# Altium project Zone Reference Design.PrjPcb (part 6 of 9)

## Sheet IO Management.SchDoc
size 431 x 279 mm; Date: Not shown in title block; ApprovedBy: Not shown in title block; CheckedBy: Not shown in title block; Author: Not shown in title block; CompanyName: Not shown in title block; Engineer: Not shown in title block; Organization: Not shown in title block; Address1: Not shown in title block; Address2: Not shown in title block; Address3: Not shown in title block; Address4: Not shown in title block; DocumentNumber: 1; Revision: Use project parameter SCH_Rev; SheetNumber: 26; SheetTotal: 30; PageSetup: Record=PageOptions¦CenterHorizontal=True¦CenterVertical=True¦PrintScale=1.00¦XCorrection=1.00¦YCorrection=1.00¦PrintKind=0¦BorderSize=5000000¦LeftOffset=0¦BottomOffset=0¦Orientation=2¦PaperLength=1000¦PaperWidth=1000¦Scale=100¦PaperSource=15¦PrintQuality=600¦MediaType=1¦DitherType=10¦PaperKind=Letter¦PrintScaleMode=1
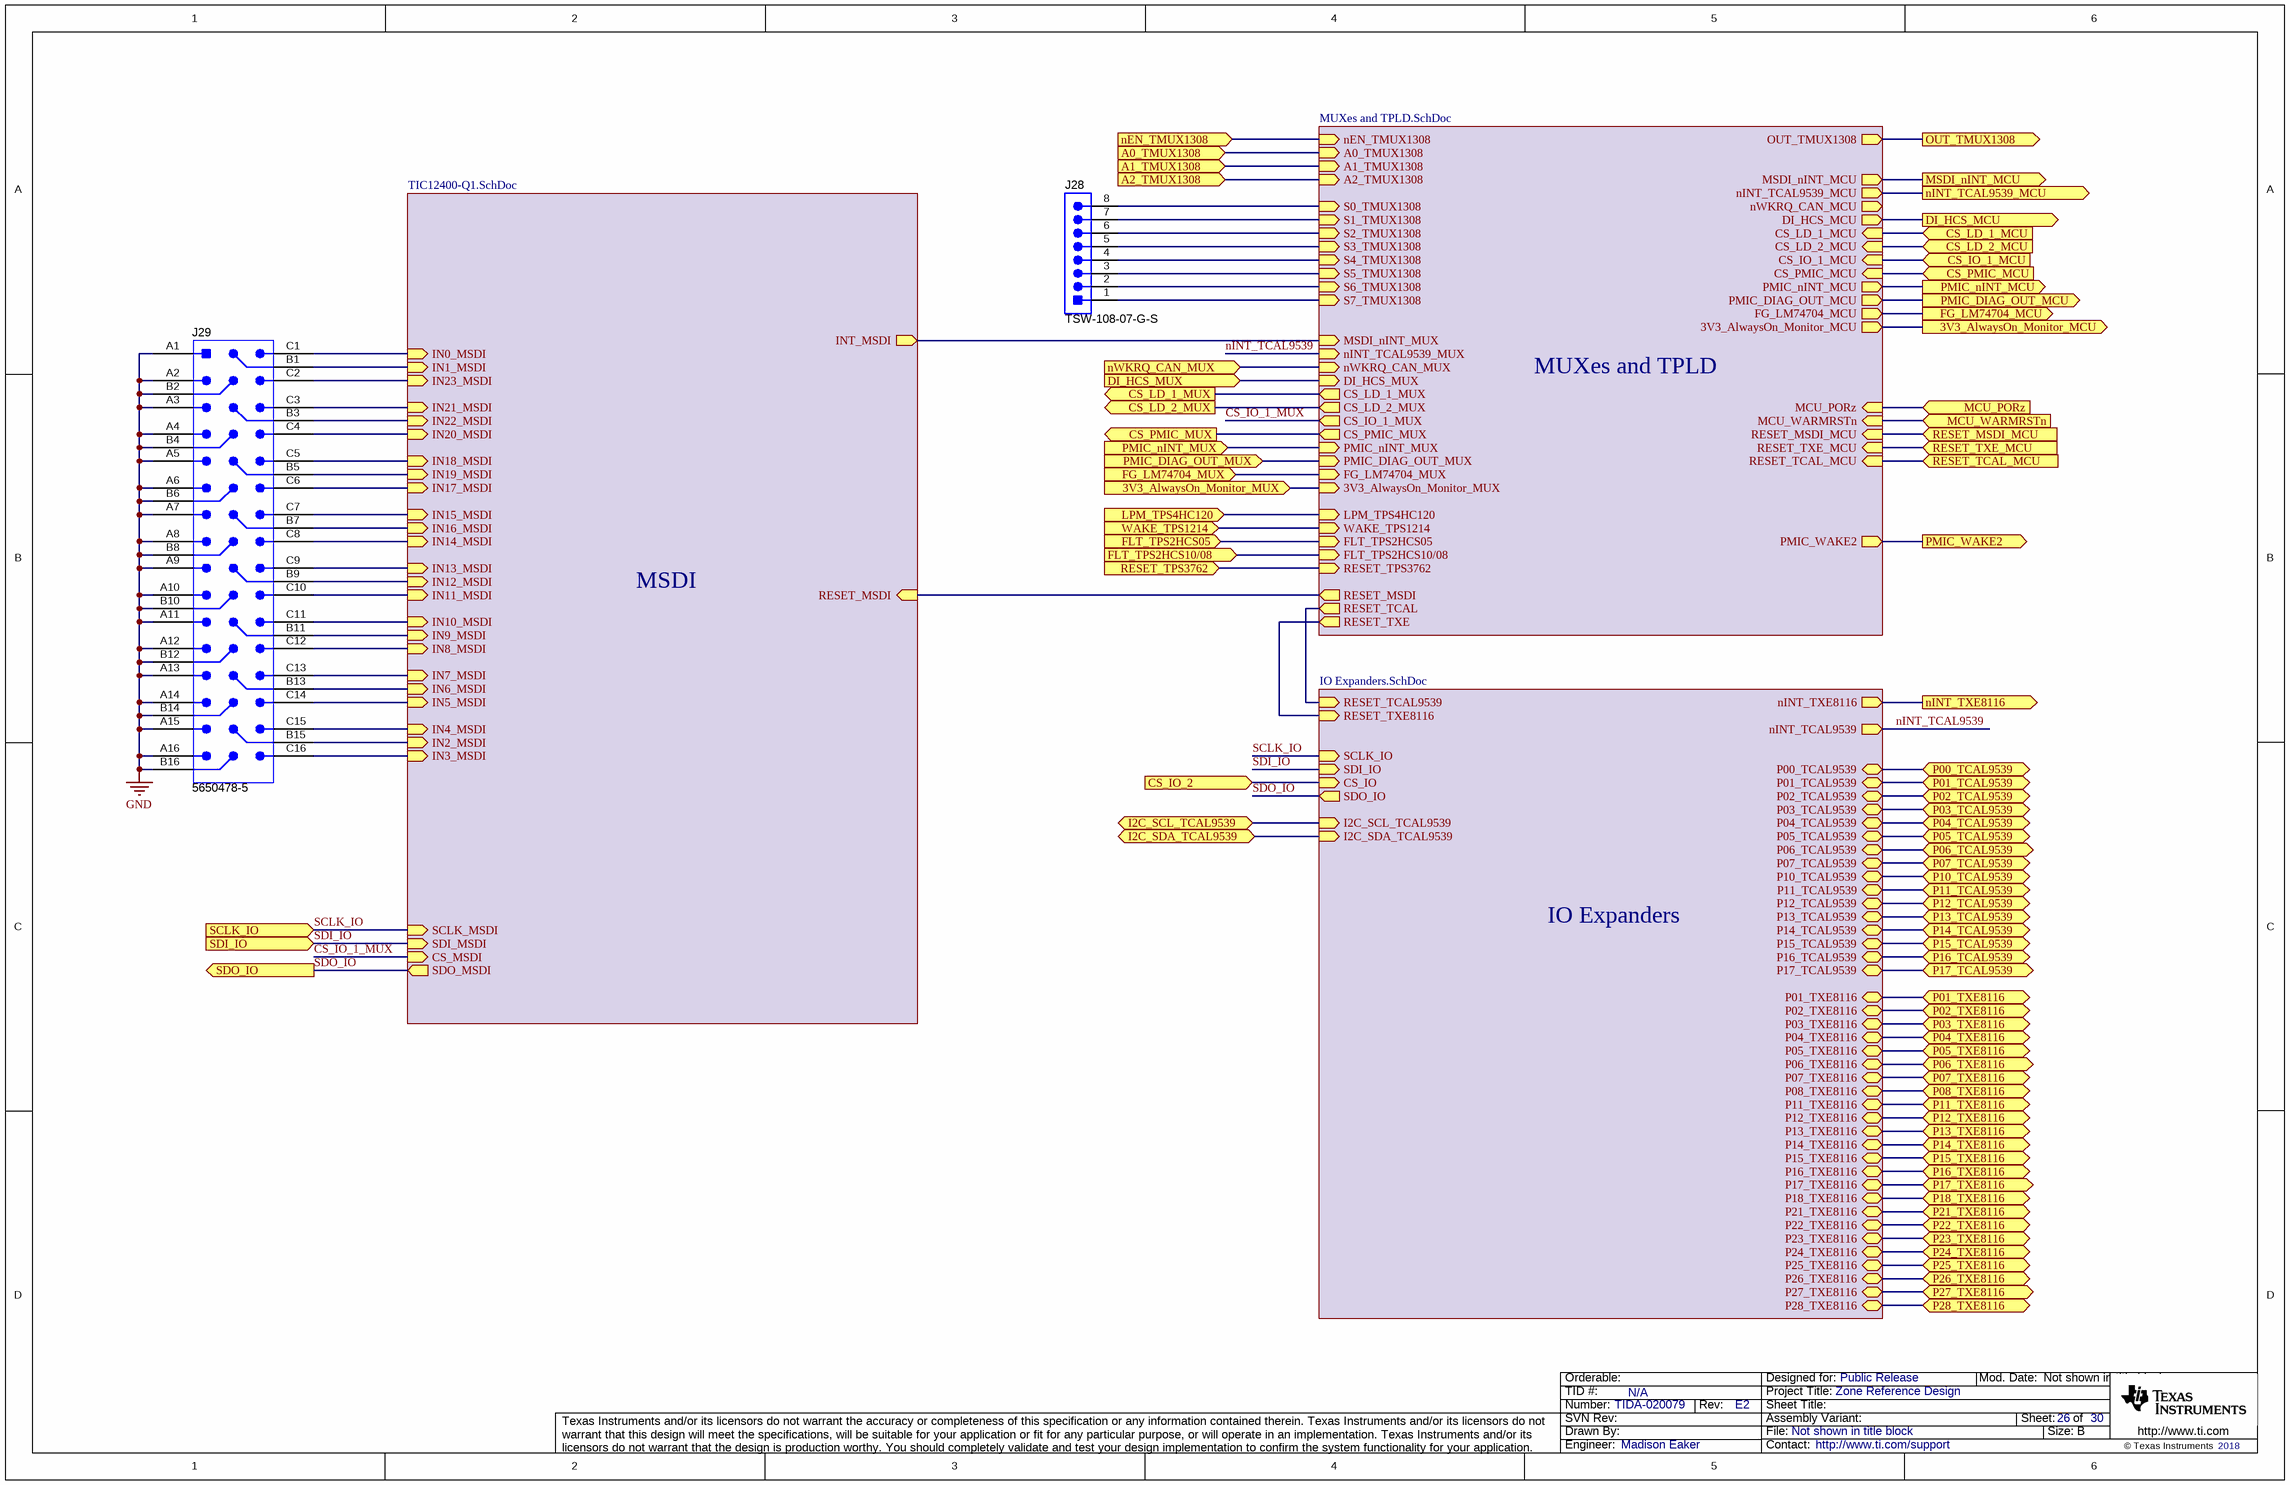
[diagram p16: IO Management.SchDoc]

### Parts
J28  TSW-108-07-G-S  [TSW-108-07-G-S]
J29  5650478-5  [TE_5650478-5]

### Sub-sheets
IO Expanders = IO Expanders.SchDoc: SCLK_IO (in), SDI_IO (in), SDO_IO (out), CS_IO (in), nINT_TXE8116 (out), RESET_TCAL9539 (in), I2C_SCL_TCAL9539 (in), I2C_SDA_TCAL9539 (in), nINT_TCAL9539 (out), RESET_TXE8116 (in), P00_TCAL9539 (bidir), P01_TCAL9539 (bidir), P02_TCAL9539 (bidir), P03_TCAL9539 (bidir), P04_TCAL9539 (bidir), P05_TCAL9539 (bidir), P06_TCAL9539 (bidir), P07_TCAL9539 (bidir), P10_TCAL9539 (bidir), P11_TCAL9539 (bidir), P12_TCAL9539 (bidir), P13_TCAL9539 (bidir), P14_TCAL9539 (bidir), P15_TCAL9539 (bidir), P16_TCAL9539 (bidir), P17_TCAL9539 (bidir), P01_TXE8116 (bidir), P02_TXE8116 (bidir), P03_TXE8116 (bidir), P04_TXE8116 (bidir), P05_TXE8116 (bidir), P06_TXE8116 (bidir), P07_TXE8116 (bidir), P11_TXE8116 (bidir), P12_TXE8116 (bidir), P13_TXE8116 (bidir), P14_TXE8116 (bidir), P15_TXE8116 (bidir), P16_TXE8116 (bidir), P17_TXE8116 (bidir), P08_TXE8116 (bidir), P18_TXE8116 (bidir), P21_TXE8116 (bidir), P22_TXE8116 (bidir), P23_TXE8116 (bidir), P24_TXE8116 (bidir), P25_TXE8116 (bidir), P26_TXE8116 (bidir), P27_TXE8116 (bidir), P28_TXE8116 (bidir)
MSDI = TIC12400-Q1.SchDoc: IN0_MSDI (in), IN1_MSDI (in), IN2_MSDI (in), IN3_MSDI (in), IN4_MSDI (in), IN5_MSDI (in), IN6_MSDI (in), IN7_MSDI (in), IN8_MSDI (in), IN9_MSDI (in), IN10_MSDI (in), IN11_MSDI (in), IN12_MSDI (in), IN13_MSDI (in), IN14_MSDI (in), IN15_MSDI (in), IN16_MSDI (in), IN17_MSDI (in), IN18_MSDI (in), IN19_MSDI (in), IN20_MSDI (in), IN21_MSDI (in), IN22_MSDI (in), IN23_MSDI (in), RESET_MSDI (in), SCLK_MSDI (in), SDI_MSDI (in), SDO_MSDI (out), CS_MSDI (in), INT_MSDI (out)
MUXes and TPLD = MUXes and TPLD.SchDoc: OUT_TMUX1308 (out), nEN_TMUX1308 (in), MSDI_nINT_MUX (in), MSDI_nINT_MCU (out), S0_TMUX1308 (in), S1_TMUX1308 (in), S2_TMUX1308 (in), S3_TMUX1308 (in), S4_TMUX1308 (in), S5_TMUX1308 (in), S6_TMUX1308 (in), S7_TMUX1308 (in), A0_TMUX1308 (in), A1_TMUX1308 (in), A2_TMUX1308 (in), PMIC_WAKE2 (out), nINT_TCAL9539_MUX (in), nINT_TCAL9539_MCU (out), MCU_PORz (in), MCU_WARMRSTn (in), RESET_MSDI_MCU (in), RESET_TXE_MCU (in), RESET_TCAL_MCU (in), RESET_MSDI (out), RESET_TCAL (out), RESET_TXE (out), DI_HCS_MUX (in), DI_HCS_MCU (out), LPM_TPS4HC120 (in), 3V3_AlwaysOn_Monitor_MUX (in), 3V3_AlwaysOn_Monitor_MCU (out), RESET_TPS3762 (in), WAKE_TPS1214 (in), FLT_TPS2HCS05 (in), FLT_TPS2HCS10/08  (in), CS_LD_1_MUX (out), CS_LD_2_MUX (out), CS_IO_1_MUX (out), CS_LD_1_MCU (in), CS_LD_2_MCU (in), CS_IO_1_MCU (in), CS_PMIC_MUX (out), CS_PMIC_MCU (in), PMIC_nINT_MUX (in), PMIC_DIAG_OUT_MUX (in), FG_LM74704_MUX (in), PMIC_nINT_MCU (out), PMIC_DIAG_OUT_MCU (out), FG_LM74704_MCU (out), nWKRQ_CAN_MUX (in), nWKRQ_CAN_MCU (out)

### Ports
3V3_AlwaysOn_Monitor_MCU (out), 3V3_AlwaysOn_Monitor_MUX (in), A0_TMUX1308 (in), A1_TMUX1308 (in), A2_TMUX1308 (in), CS_IO_1_MCU (in), CS_IO_2 (in), CS_LD_1_MCU (in), CS_LD_1_MUX (out), CS_LD_2_MCU (in), CS_LD_2_MUX (out), CS_PMIC_MCU (in), CS_PMIC_MUX (out), DI_HCS_MCU (out), DI_HCS_MUX (in), FG_LM74704_MCU (out), FG_LM74704_MUX (in), FLT_TPS2HCS05 (in), FLT_TPS2HCS10/08  (in), I2C_SCL_TCAL9539 (bidir), I2C_SDA_TCAL9539 (bidir), LPM_TPS4HC120 (in), MCU_PORz (in), MCU_WARMRSTn (in), MSDI_nINT_MCU (out), nEN_TMUX1308 (in), nINT_TCAL9539_MCU (out), nINT_TXE8116 (out), nWKRQ_CAN_MUX (in), OUT_TMUX1308 (out), P00_TCAL9539 (bidir), P01_TCAL9539 (bidir), P01_TXE8116 (bidir), P02_TCAL9539 (bidir), P02_TXE8116 (bidir), P03_TCAL9539 (bidir), P03_TXE8116 (bidir), P04_TCAL9539 (bidir), P04_TXE8116 (bidir), P05_TCAL9539 (bidir), P05_TXE8116 (bidir), P06_TCAL9539 (bidir), P06_TXE8116 (bidir), P07_TCAL9539 (bidir), P07_TXE8116 (bidir), P08_TXE8116 (bidir), P10_TCAL9539 (bidir), P11_TCAL9539 (bidir), P11_TXE8116 (bidir), P12_TCAL9539 (bidir), P12_TXE8116 (bidir), P13_TCAL9539 (bidir), P13_TXE8116 (bidir), P14_TCAL9539 (bidir), P14_TXE8116 (bidir), P15_TCAL9539 (bidir), P15_TXE8116 (bidir), P16_TCAL9539 (bidir), P16_TXE8116 (bidir), P17_TCAL9539 (bidir), P17_TXE8116 (bidir), P18_TXE8116 (bidir), P21_TXE8116 (bidir), P22_TXE8116 (bidir), P23_TXE8116 (bidir), P24_TXE8116 (bidir), P25_TXE8116 (bidir), P26_TXE8116 (bidir), P27_TXE8116 (bidir), P28_TXE8116 (bidir), PMIC_DIAG_OUT_MCU (out), PMIC_DIAG_OUT_MUX (in), PMIC_nINT_MCU (out), PMIC_nINT_MUX (in), PMIC_WAKE2 (out), RESET_MSDI_MCU (in), RESET_TCAL_MCU (in), RESET_TPS3762 (in), RESET_TXE_MCU (in), SCLK_IO (in), SDI_IO (in), SDO_IO (out), WAKE_TPS1214 (in)

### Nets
GND: J29.A1 J29.A2 J29.A3 J29.A4 J29.A5 J29.A6 J29.A7 J29.A8 J29.A9 J29.A10 J29.A11 J29.A12 J29.A13 J29.A14 J29.A15 J29.A16 J29.B2 J29.B4 J29.B6 J29.B8 J29.B10 J29.B12 J29.B14 J29.B16
3V3_ADC: port 3V3_AlwaysOn_Monitor_MUX, sheet MUXes and TPLD/3V3_AlwaysOn_Monitor_MUX
3V3_AlwaysOn_Monitor_MCU: port 3V3_AlwaysOn_Monitor_MCU, sheet MUXes and TPLD/3V3_AlwaysOn_Monitor_MCU
A0_TMUX1308: port A0_TMUX1308, sheet MUXes and TPLD/A0_TMUX1308
A1_TMUX1308: port A1_TMUX1308, sheet MUXes and TPLD/A1_TMUX1308
A2_TMUX1308: port A2_TMUX1308, sheet MUXes and TPLD/A2_TMUX1308
ADC1_AIN0: port OUT_TMUX1308, sheet MUXes and TPLD/OUT_TMUX1308
BRAKE_DRV8714: port P07_TXE8116, sheet IO Expanders/P07_TXE8116
ClassD_AMP_FAULT: port P02_TXE8116, sheet IO Expanders/P02_TXE8116
ClassD_AMP_SHTDN: port P03_TXE8116, sheet IO Expanders/P03_TXE8116
ClassD_AMP_STBY: port P01_TXE8116, sheet IO Expanders/P01_TXE8116
CS_IO: port CS_IO_2, sheet IO Expanders/CS_IO
CS_IO_1_MCU: port CS_IO_1_MCU, sheet MUXes and TPLD/CS_IO_1_MCU
CS_IO_1_MUX: sheet MUXes and TPLD/CS_IO_1_MUX, sheet MSDI/CS_MSDI
CS_LD_1: port CS_LD_1_MUX, sheet MUXes and TPLD/CS_LD_1_MUX
CS_LD_1_MCU: port CS_LD_1_MCU, sheet MUXes and TPLD/CS_LD_1_MCU
CS_LD_2: port CS_LD_2_MUX, sheet MUXes and TPLD/CS_LD_2_MUX
CS_PMIC: port CS_PMIC_MUX, sheet MUXes and TPLD/CS_PMIC_MUX
CS_PMIC_MCU: port CS_PMIC_MCU, sheet MUXes and TPLD/CS_PMIC_MCU
DI_HCS: port DI_HCS_MUX, sheet MUXes and TPLD/DI_HCS_MUX
DI_HCS_MCU: port DI_HCS_MCU, sheet MUXes and TPLD/DI_HCS_MCU
DIAGEN_TPS1HC04: port P27_TXE8116, sheet IO Expanders/P27_TXE8116
DIAGEN_TPS1HC30: port P11_TXE8116, sheet IO Expanders/P11_TXE8116
DIAGEN_TPS2HC08: port P24_TXE8116, sheet IO Expanders/P24_TXE8116
DIAGEN_TPS4HC120: port P14_TCAL9539, sheet IO Expanders/P14_TCAL9539
DRVOFF_DRV8145: port P05_TXE8116, sheet IO Expanders/P05_TXE8116
EN1_TPS2HC08: port P21_TXE8116, sheet IO Expanders/P21_TXE8116
EN1_TPS4HC120: port P10_TCAL9539, sheet IO Expanders/P10_TCAL9539
EN2_TPS2HC08: port P22_TXE8116, sheet IO Expanders/P22_TXE8116
EN2_TPS4HC120: port P11_TCAL9539, sheet IO Expanders/P11_TCAL9539
EN3_TPS4HC120: port P12_TCAL9539, sheet IO Expanders/P12_TCAL9539
EN4_TPS4HC120: port P13_TCAL9539, sheet IO Expanders/P13_TCAL9539
EN_ETH: port P01_TCAL9539, sheet IO Expanders/P01_TCAL9539
EN_TPS1HC04: port P26_TXE8116, sheet IO Expanders/P26_TXE8116
EN_TPS1HC30: port P17_TXE8116, sheet IO Expanders/P17_TXE8116
EN_TPS1214: port P06_TCAL9539, sheet IO Expanders/P06_TCAL9539
EPWM5_B: port nINT_TCAL9539_MCU, sheet MUXes and TPLD/nINT_TCAL9539_MCU
EPWM9_A: port RESET_TCAL_MCU, sheet MUXes and TPLD/RESET_TCAL_MCU
EQEP0_B: port MSDI_nINT_MCU, sheet MUXes and TPLD/MSDI_nINT_MCU
EQEP0_STROBE: port nEN_TMUX1308, sheet MUXes and TPLD/nEN_TMUX1308
FETGOOD: port FG_LM74704_MUX, sheet MUXes and TPLD/FG_LM74704_MUX
FG_LM74704_MCU: port FG_LM74704_MCU, sheet MUXes and TPLD/FG_LM74704_MCU
FLT/: port P07_TCAL9539, sheet IO Expanders/P07_TCAL9539
FLT_I_TPS1211: port P16_TXE8116, sheet IO Expanders/P16_TXE8116
FLT_T_TPS1211: port P15_TXE8116, sheet IO Expanders/P15_TXE8116
FLT_TPS2HCS05: port P04_TCAL9539, port FLT_TPS2HCS05, sheet MUXes and TPLD/FLT_TPS2HCS05, sheet IO Expanders/P04_TCAL9539
FLT_TPS2HCS10/08: port P05_TCAL9539, port FLT_TPS2HCS10/08 , sheet MUXes and TPLD/FLT_TPS2HCS10/08 , sheet IO Expanders/P05_TCAL9539
GPIO14: port PMIC_DIAG_OUT_MCU, sheet MUXes and TPLD/PMIC_DIAG_OUT_MCU
GPIO81: port nINT_TXE8116, sheet IO Expanders/nINT_TXE8116
GPIO112: port RESET_MSDI_MCU, sheet MUXes and TPLD/RESET_MSDI_MCU
GPIO124: port RESET_TXE_MCU, sheet MUXes and TPLD/RESET_TXE_MCU
I2C0_SCL: port I2C_SCL_TCAL9539, sheet IO Expanders/I2C_SCL_TCAL9539
I2C0_SDA: port I2C_SDA_TCAL9539, sheet IO Expanders/I2C_SDA_TCAL9539
IN0_MSDI: J29.C1 ; sheet MSDI/IN0_MSDI
IN1_MSDI: J29.B1 ; sheet MSDI/IN1_MSDI
IN2_MSDI: J29.B15 ; sheet MSDI/IN2_MSDI
IN3_MSDI: J29.C16 ; sheet MSDI/IN3_MSDI
IN4_MSDI: J29.C15 ; sheet MSDI/IN4_MSDI
IN5_MSDI: J29.C14 ; sheet MSDI/IN5_MSDI
IN6_MSDI: J29.B13 ; sheet MSDI/IN6_MSDI
IN7_MSDI: J29.C13 ; sheet MSDI/IN7_MSDI
IN8_MSDI: J29.C12 ; sheet MSDI/IN8_MSDI
IN9_MSDI: J29.B11 ; sheet MSDI/IN9_MSDI
IN10_MSDI: J29.C11 ; sheet MSDI/IN10_MSDI
IN11_MSDI: J29.C10 ; sheet MSDI/IN11_MSDI
IN12_MSDI: J29.B9 ; sheet MSDI/IN12_MSDI
IN13_MSDI: J29.C9 ; sheet MSDI/IN13_MSDI
IN14_MSDI: J29.C8 ; sheet MSDI/IN14_MSDI
IN15_MSDI: J29.C7 ; sheet MSDI/IN15_MSDI
IN16_MSDI: J29.B7 ; sheet MSDI/IN16_MSDI
IN17_MSDI: J29.C6 ; sheet MSDI/IN17_MSDI
IN18_MSDI: J29.C5 ; sheet MSDI/IN18_MSDI
IN19_MSDI: J29.B5 ; sheet MSDI/IN19_MSDI
IN20_MSDI: J29.C4 ; sheet MSDI/IN20_MSDI
IN21_MSDI: J29.C3 ; sheet MSDI/IN21_MSDI
IN22_MSDI: J29.B3 ; sheet MSDI/IN22_MSDI
IN23_MSDI: J29.C2 ; sheet MSDI/IN23_MSDI
INP_G_TPS1211: port P14_TXE8116, sheet IO Expanders/P14_TXE8116
INP_TPS1211: port P13_TXE8116, sheet IO Expanders/P13_TXE8116
INT_MSDI: sheet MUXes and TPLD/MSDI_nINT_MUX, sheet MSDI/INT_MSDI
LATCH_TPS1HC30: port P08_TXE8116, sheet IO Expanders/P08_TXE8116
LPM_TPS4HC120: port P03_TCAL9539, port LPM_TPS4HC120, sheet MUXes and TPLD/LPM_TPS4HC120, sheet IO Expanders/P03_TCAL9539
MCU_PORz: port MCU_PORz, sheet MUXes and TPLD/MCU_PORz
MCU_WARMRSTn: port MCU_WARMRSTn, sheet MUXes and TPLD/MCU_WARMRSTn
nFAULT_DRV8145: port P06_TXE8116, sheet IO Expanders/P06_TXE8116
nFAULT_TPS1HC04: port P28_TXE8116, sheet IO Expanders/P28_TXE8116
nFAULT_TPS1HC30: port P18_TXE8116, sheet IO Expanders/P18_TXE8116
nFAULT_TPS2HC08: port P25_TXE8116, sheet IO Expanders/P25_TXE8116
nFAULT_TPS4HC120: port P17_TCAL9539, sheet IO Expanders/P17_TCAL9539
nFLT_DRV8714: port P12_TXE8116, sheet IO Expanders/P12_TXE8116
nINT_TCAL9539: sheet MUXes and TPLD/nINT_TCAL9539_MUX, sheet IO Expanders/nINT_TCAL9539
nSLEEP_DRV81242: port P04_TXE8116, sheet IO Expanders/P04_TXE8116
nWKRQ_CAN_MUX: port nWKRQ_CAN_MUX, sheet MUXes and TPLD/nWKRQ_CAN_MUX
P15_TCAL9539: port P15_TCAL9539, sheet IO Expanders/P15_TCAL9539
P16_TCAL9539: port P16_TCAL9539, sheet IO Expanders/P16_TCAL9539
P23_TXE8116: port P23_TXE8116, sheet IO Expanders/P23_TXE8116
PMIC_DIAG: port PMIC_DIAG_OUT_MUX, sheet MUXes and TPLD/PMIC_DIAG_OUT_MUX
PMIC_nINT: port PMIC_nINT_MUX, sheet MUXes and TPLD/PMIC_nINT_MUX
RESET_ETH: port P00_TCAL9539, sheet IO Expanders/P00_TCAL9539
RESET_MSDI: sheet MUXes and TPLD/RESET_MSDI, sheet MSDI/RESET_MSDI
RESET_TCAL: sheet MUXes and TPLD/RESET_TCAL, sheet IO Expanders/RESET_TCAL9539
RESET_TPS: port RESET_TPS3762, sheet MUXes and TPLD/RESET_TPS3762
RESET_TXE: sheet MUXes and TPLD/RESET_TXE, sheet IO Expanders/RESET_TXE8116
S0_TMUX1308: J28.8 ; sheet MUXes and TPLD/S0_TMUX1308
S1_TMUX1308: J28.7 ; sheet MUXes and TPLD/S1_TMUX1308
S2_TMUX1308: J28.6 ; sheet MUXes and TPLD/S2_TMUX1308
S3_TMUX1308: J28.5 ; sheet MUXes and TPLD/S3_TMUX1308
S4_TMUX1308: J28.4 ; sheet MUXes and TPLD/S4_TMUX1308
S5_TMUX1308: J28.3 ; sheet MUXes and TPLD/S5_TMUX1308
S6_TMUX1308: J28.2 ; sheet MUXes and TPLD/S6_TMUX1308
S7_TMUX1308: J28.1 ; sheet MUXes and TPLD/S7_TMUX1308
SCLK_IO: port SCLK_IO, sheet MSDI/SCLK_MSDI, sheet IO Expanders/SCLK_IO
SDI_IO: port SDI_IO, sheet MSDI/SDI_MSDI, sheet IO Expanders/SDI_IO
SDO_IO: port SDO_IO, sheet MSDI/SDO_MSDI, sheet IO Expanders/SDO_IO
SPI0_D0: port PMIC_nINT_MCU, sheet MUXes and TPLD/PMIC_nINT_MCU
SPI7_CS2: port CS_LD_2_MCU, sheet MUXes and TPLD/CS_LD_2_MCU
WAKE: port P02_TCAL9539, port WAKE_TPS1214, sheet MUXes and TPLD/WAKE_TPS1214, sheet IO Expanders/P02_TCAL9539
WAKE2: port PMIC_WAKE2, sheet MUXes and TPLD/PMIC_WAKE2

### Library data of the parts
J28 = CMP-0075419-1: Header, 100mil, 8x1, Gold, TH; Manufacturer: Samtec; Pitch_mm: 2.54; Cert_VDE: N; Gender: Male; Cert_CSA: Y; Voltage_V: 550V; Green_REACh: Passed; Current_A: 6.3A; CT: False; Green_Lifecycle: Active; Row_Count: 1; CNHeader: True
J29 = CMP-0054957-1: Header, 2.54mml, 16x3, Gold, TH; Manufacturer: TE Connectivity; CNHeader: TRUE; Shrouded: Y; Gender: Male; Row_Count: 3; RowSpacing_mm: 2.54; CT: FALSE

## Sheet MUXes and TPLD.SchDoc
size 431 x 279 mm; Date: Not shown in title block; ApprovedBy: Not shown in title block; CheckedBy: Not shown in title block; Author: Not shown in title block; CompanyName: Not shown in title block; Engineer: Not shown in title block; Organization: Not shown in title block; Address1: Not shown in title block; Address2: Not shown in title block; Address3: Not shown in title block; Address4: Not shown in title block; DocumentNumber: 1; Revision: Use project parameter SCH_Rev; SheetNumber: 28; SheetTotal: 30; PageSetup: Record=PageOptions¦CenterHorizontal=True¦CenterVertical=True¦PrintScale=1.00¦XCorrection=1.00¦YCorrection=1.00¦PrintKind=0¦BorderSize=5000000¦LeftOffset=0¦BottomOffset=0¦Orientation=2¦PaperLength=1000¦PaperWidth=1000¦Scale=100¦PaperSource=15¦PrintQuality=600¦MediaType=1¦DitherType=10¦PaperKind=Letter¦PrintScaleMode=1
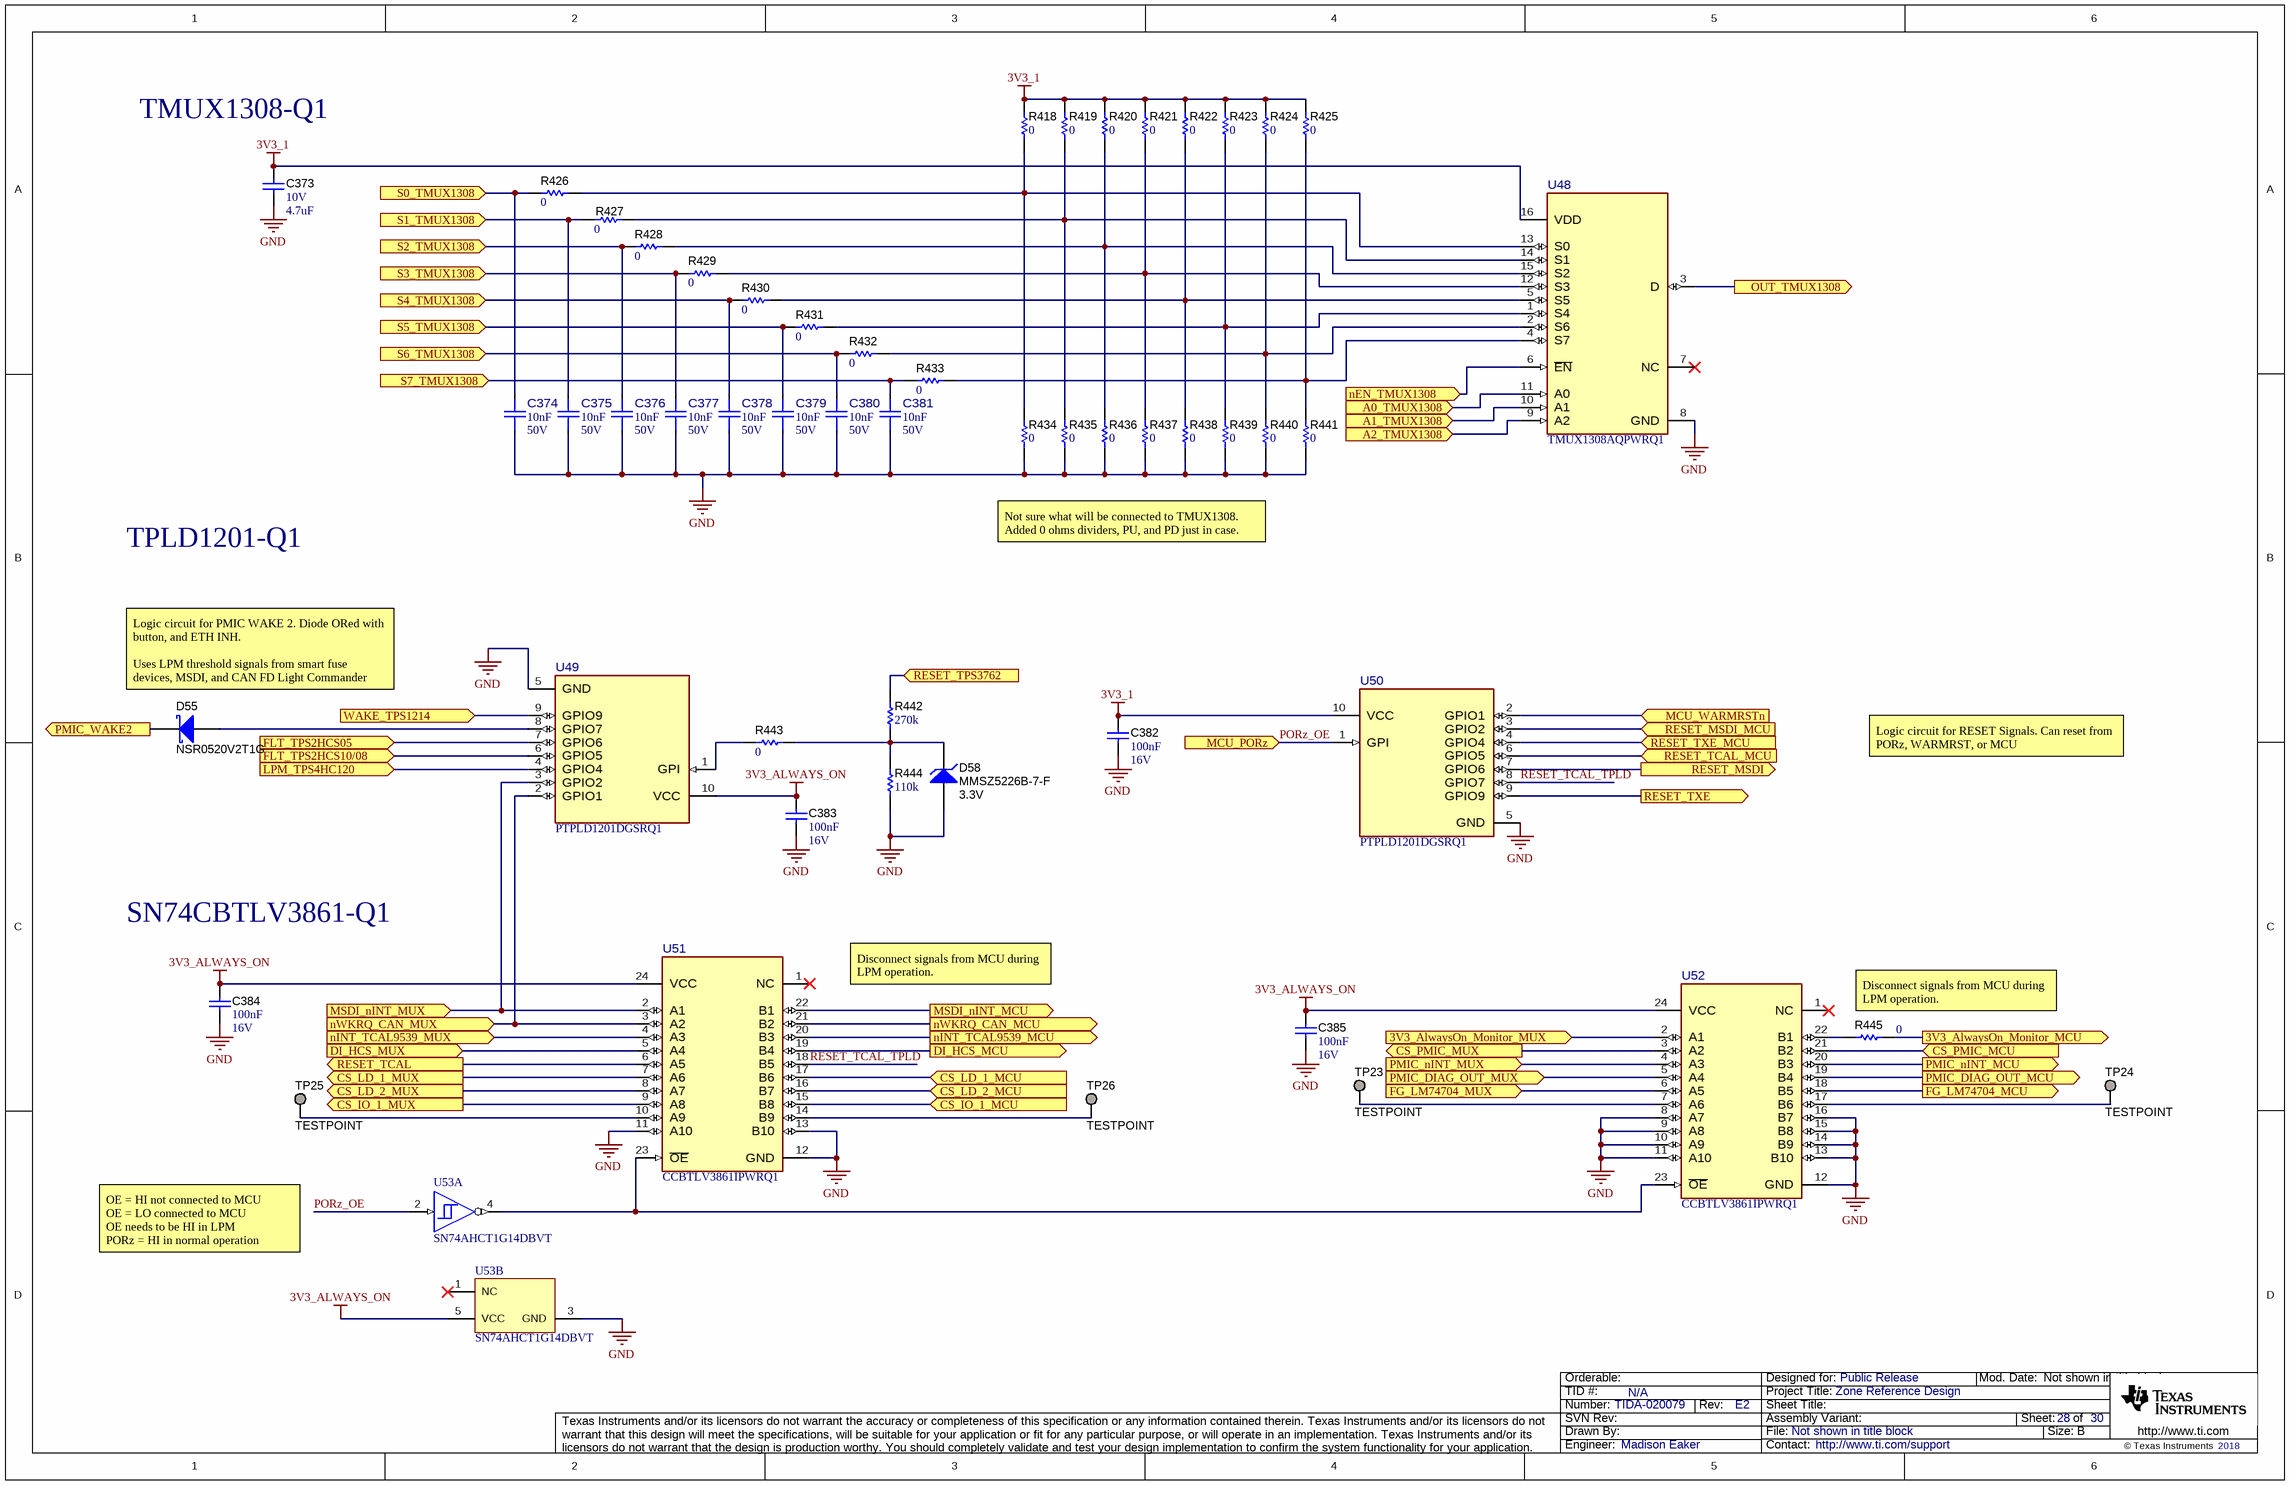
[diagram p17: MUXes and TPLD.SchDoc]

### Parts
C373  VDC_V: 10V  ValueDisplayed: 4.7uF  [0603]  (hidden comment: C0603C475K8PACTU)
C374  Cap_F: 10nF  VDC_V: 50V  [FP-GCE188R71H103KA01D_0603-MFG]  (hidden comment: GCE188R71H103KA01D)
C375  Cap_F: 10nF  VDC_V: 50V  [FP-GCE188R71H103KA01D_0603-MFG]  (hidden comment: GCE188R71H103KA01D)
C376  Cap_F: 10nF  VDC_V: 50V  [FP-GCE188R71H103KA01D_0603-MFG]  (hidden comment: GCE188R71H103KA01D)
C377  Cap_F: 10nF  VDC_V: 50V  [FP-GCE188R71H103KA01D_0603-MFG]  (hidden comment: GCE188R71H103KA01D)
C378  Cap_F: 10nF  VDC_V: 50V  [FP-GCE188R71H103KA01D_0603-MFG]  (hidden comment: GCE188R71H103KA01D)
C379  Cap_F: 10nF  VDC_V: 50V  [FP-GCE188R71H103KA01D_0603-MFG]  (hidden comment: GCE188R71H103KA01D)
C380  Cap_F: 10nF  VDC_V: 50V  [FP-GCE188R71H103KA01D_0603-MFG]  (hidden comment: GCE188R71H103KA01D)
C381  Cap_F: 10nF  VDC_V: 50V  [FP-GCE188R71H103KA01D_0603-MFG]  (hidden comment: GCE188R71H103KA01D)
C382  Cap_F: 100nF  VDC_V: 16V  [0603]  (hidden comment: GCM188R71C104KA37J)
C383  Cap_F: 100nF  VDC_V: 16V  [0603]  (hidden comment: GCM188R71C104KA37J)
C384  Cap_F: 100nF  VDC_V: 16V  [0603]  (hidden comment: GCM188R71C104KA37J)
C385  Cap_F: 100nF  VDC_V: 16V  [0603]  (hidden comment: GCM188R71C104KA37J)
D55  NSR0520V2T1G  [SOD-523]
D58  MMSZ5226B-7-F  value 3.3V  [SOD-123]
R418  ValueDisplayed: 0  [0603]  (hidden comment: CRCW06030000Z0EA)
R419  ValueDisplayed: 0  [0603]  (hidden comment: CRCW06030000Z0EA)
R420  ValueDisplayed: 0  [0603]  (hidden comment: CRCW06030000Z0EA)
R421  ValueDisplayed: 0  [0603]  (hidden comment: CRCW06030000Z0EA)
R422  ValueDisplayed: 0  [0603]  (hidden comment: CRCW06030000Z0EA)
R423  ValueDisplayed: 0  [0603]  (hidden comment: CRCW06030000Z0EA)
R424  ValueDisplayed: 0  [0603]  (hidden comment: CRCW06030000Z0EA)
R425  ValueDisplayed: 0  [0603]  (hidden comment: CRCW06030000Z0EA)
R426  ValueDisplayed: 0  [0603]  (hidden comment: CRCW06030000Z0EA)
R427  ValueDisplayed: 0  [0603]  (hidden comment: CRCW06030000Z0EA)
R428  ValueDisplayed: 0  [0603]  (hidden comment: CRCW06030000Z0EA)
R429  ValueDisplayed: 0  [0603]  (hidden comment: CRCW06030000Z0EA)
R430  ValueDisplayed: 0  [0603]  (hidden comment: CRCW06030000Z0EA)
R431  ValueDisplayed: 0  [0603]  (hidden comment: CRCW06030000Z0EA)
R432  ValueDisplayed: 0  [0603]  (hidden comment: CRCW06030000Z0EA)
R433  ValueDisplayed: 0  [0603]  (hidden comment: CRCW06030000Z0EA)
R434  ValueDisplayed: 0  [0603]  (hidden comment: CRCW06030000Z0EA)
R435  ValueDisplayed: 0  [0603]  (hidden comment: CRCW06030000Z0EA)
R436  ValueDisplayed: 0  [0603]  (hidden comment: CRCW06030000Z0EA)
R437  ValueDisplayed: 0  [0603]  (hidden comment: CRCW06030000Z0EA)
R438  ValueDisplayed: 0  [0603]  (hidden comment: CRCW06030000Z0EA)
R439  ValueDisplayed: 0  [0603]  (hidden comment: CRCW06030000Z0EA)
R440  ValueDisplayed: 0  [0603]  (hidden comment: CRCW06030000Z0EA)
R441  ValueDisplayed: 0  [0603]  (hidden comment: CRCW06030000Z0EA)
R442  ValueDisplayed: 270k  [0603]  (hidden comment: CRCW0603270KJNEA)
R443  ValueDisplayed: 0  [0603]  (hidden comment: CRCW06030000Z0EA)
R444  ValueDisplayed: 110k  [0603]  (hidden comment: CRCW0603110KFKEA)
R445  ValueDisplayed: 0  [0603]  (hidden comment: CRCW06030000Z0EA)
TP23  TESTPOINT  [TP_25MIL-SMT]  (no BOM)
TP24  TESTPOINT  [TP_25MIL-SMT]  (no BOM)
TP25  TESTPOINT  [TP_25MIL-SMT]  (no BOM)
TP26  TESTPOINT  [TP_25MIL-SMT]  (no BOM)
U48  TMUX1308AQPWRQ1  [PW0016A-MFG]
U49  PTPLD1201DGSRQ1  [DGS0010A-MFG]
U50  PTPLD1201DGSRQ1  [DGS0010A-MFG]
U51  CCBTLV3861IPWRQ1  [PW0024A-MFG]
U52  CCBTLV3861IPWRQ1  [PW0024A-MFG]
U53  SN74AHCT1G14DBVT  [DBV0005A_N]  (parts A,B of 2)

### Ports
3V3_AlwaysOn_Monitor_MCU (out), 3V3_AlwaysOn_Monitor_MUX (in), A0_TMUX1308 (in), A1_TMUX1308 (in), A2_TMUX1308 (in), CS_IO_1_MCU (in), CS_IO_1_MUX (out), CS_LD_1_MCU (in), CS_LD_1_MUX (out), CS_LD_2_MCU (in), CS_LD_2_MUX (out), CS_PMIC_MCU (in), CS_PMIC_MUX (out), DI_HCS_MCU (out), DI_HCS_MUX (in), FG_LM74704_MCU (out), FG_LM74704_MUX (in), FLT_TPS2HCS05 (in), FLT_TPS2HCS10/08  (in), LPM_TPS4HC120 (in), MCU_PORz (in), MCU_WARMRSTn (in), MSDI_nINT_MCU (out), MSDI_nINT_MUX (in), nEN_TMUX1308 (in), nINT_TCAL9539_MCU (out), nINT_TCAL9539_MUX (in), nWKRQ_CAN_MCU (out), nWKRQ_CAN_MUX (in), OUT_TMUX1308 (out), PMIC_DIAG_OUT_MCU (out), PMIC_DIAG_OUT_MUX (in), PMIC_nINT_MCU (out), PMIC_nINT_MUX (in), PMIC_WAKE2 (out), RESET_MSDI (out), RESET_MSDI_MCU (in), RESET_TCAL (out), RESET_TCAL_MCU (in), RESET_TPS3762 (in), RESET_TXE (out), RESET_TXE_MCU (in), S0_TMUX1308 (in), S1_TMUX1308 (in), S2_TMUX1308 (in), S3_TMUX1308 (in), S4_TMUX1308 (in), S5_TMUX1308 (in), S6_TMUX1308 (in), S7_TMUX1308 (in), WAKE_TPS1214 (in)

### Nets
3V3_1: C373.2 C382.1 R418.2 R419.2 R420.2 R421.2 R422.2 R423.2 R424.2 R425.2 U48.16(VDD) U50.10(VCC)
3V3_ALWAYS_ON: C383.1 C384.1 C385.1 U49.10(VCC) U51.24(VCC) U52.24(VCC) U53.5(VCC)
GND: C373.1 C374.1 C375.1 C376.1 C377.1 C378.1 C379.1 C380.1 C381.1 C382.2 C383.2 C384.2 C385.2 D58.2(A) R434.1 R435.1 R436.1 R437.1 R438.1 R439.1 R440.1 R441.1 R444.1 U48.8(GND) U49.5(GND) U50.5(GND) U51.11(A10) U51.12(GND) U51.13(B10) U52.8(A7) U52.9(A8) U52.10(A9) U52.11(A10) U52.12(GND) U52.13(B10) U52.14(B9) U52.15(B8) U52.16(B7) U53.3(GND)
3V3_ADC: U52.2(A1) ; port 3V3_AlwaysOn_Monitor_MUX
3V3_AlwaysOn_Monitor_MCU: R445.1 ; port 3V3_AlwaysOn_Monitor_MCU
A0_TMUX1308: U48.11(A0) ; port A0_TMUX1308
A1_TMUX1308: U48.10(A1) ; port A1_TMUX1308
A2_TMUX1308: U48.9(A2) ; port A2_TMUX1308
ADC1_AIN0: U48.3(D) ; port OUT_TMUX1308
CS_IO_1_MCU: U51.15(B8) ; port CS_IO_1_MCU
CS_IO_1_MUX: U51.9(A8) ; port CS_IO_1_MUX
CS_LD_1: U51.7(A6) ; port CS_LD_1_MUX
CS_LD_1_MCU: U51.17(B6) ; port CS_LD_1_MCU
CS_LD_2: U51.8(A7) ; port CS_LD_2_MUX
CS_PMIC: U52.3(A2) ; port CS_PMIC_MUX
CS_PMIC_MCU: U52.21(B2) ; port CS_PMIC_MCU
DI_HCS: U51.5(A4) ; port DI_HCS_MUX
DI_HCS_MCU: U51.19(B4) ; port DI_HCS_MCU
EPWM5_B: U51.20(B3) ; port nINT_TCAL9539_MCU
EPWM9_A: U50.6(GPIO5) ; port RESET_TCAL_MCU
EQEP0_B: U51.22(B1) ; port MSDI_nINT_MCU
EQEP0_STROBE: U48.6(~{EN}) ; port nEN_TMUX1308
FETGOOD: U52.6(A5) ; port FG_LM74704_MUX
FG_LM74704_MCU: U52.18(B5) ; port FG_LM74704_MCU
FLT_TPS2HCS05: U49.7(GPIO6) ; port FLT_TPS2HCS05
FLT_TPS2HCS10/08: U49.6(GPIO5) ; port FLT_TPS2HCS10/08 
GPIO14: U52.19(B4) ; port PMIC_DIAG_OUT_MCU
GPIO112: U50.3(GPIO2) ; port RESET_MSDI_MCU
GPIO124: U50.4(GPIO4) ; port RESET_TXE_MCU
INT_MSDI: U49.3(GPIO2) U51.2(A1) ; port MSDI_nINT_MUX
LPM_TPS4HC120: U49.4(GPIO4) ; port LPM_TPS4HC120
MCU_WARMRSTn: U50.2(GPIO1) ; port MCU_WARMRSTn
nINT_TCAL9539: U51.4(A3) ; port nINT_TCAL9539_MUX
nWKRQ_CAN_MCU: U51.21(B2) ; port nWKRQ_CAN_MCU
nWKRQ_CAN_MUX: U49.2(GPIO1) U51.3(A2) ; port nWKRQ_CAN_MUX
PMIC_DIAG: U52.5(A4) ; port PMIC_DIAG_OUT_MUX
PMIC_nINT: U52.4(A3) ; port PMIC_nINT_MUX
PORz_OE: U50.1(GPI) U53.2(A) ; port MCU_PORz  [project net MCU_PORz]
RESET_MSDI: U50.7(GPIO6) ; port RESET_MSDI
RESET_TCAL: U51.6(A5) ; port RESET_TCAL
RESET_TCAL_TPLD: U50.8(GPIO7) U51.18(B5)  [project net RESET_TCAL_TPLD_28]
RESET_TPS: R442.2 ; port RESET_TPS3762
RESET_TXE: U50.9(GPIO9) ; port RESET_TXE
S0_TMUX1308: C374.2 R426.1 ; port S0_TMUX1308
S1_TMUX1308: C375.2 R427.1 ; port S1_TMUX1308
S2_TMUX1308: C376.2 R428.1 ; port S2_TMUX1308
S3_TMUX1308: C377.2 R429.1 ; port S3_TMUX1308
S4_TMUX1308: C378.2 R430.1 ; port S4_TMUX1308
S5_TMUX1308: C379.2 R431.1 ; port S5_TMUX1308
S6_TMUX1308: C380.2 R432.1 ; port S6_TMUX1308
S7_TMUX1308: C381.2 R433.1 ; port S7_TMUX1308
SPI0_D0: U52.20(B3) ; port PMIC_nINT_MCU
SPI7_CS2: U51.16(B7) ; port CS_LD_2_MCU
WAKE: U49.9(GPIO9) ; port WAKE_TPS1214
WAKE2: D55.1(K) ; port PMIC_WAKE2
NetD55_2: D55.2(A) U49.8(GPIO7)
NetD58_1: D58.1(K) R442.1 R443.1 R444.2
NetR418_1: R418.1 R426.2 R434.2 U48.13(S0)
NetR419_1: R419.1 R427.2 R435.2 U48.14(S1)
NetR420_1: R420.1 R428.2 R436.2 U48.15(S2)
NetR421_1: R421.1 R429.2 R437.2 U48.12(S3)
NetR422_1: R422.1 R430.2 R438.2 U48.5(S5)
NetR423_1: R423.1 R431.2 R439.2 U48.1(S4)
NetR424_1: R424.1 R432.2 R440.2 U48.2(S6)
NetR425_1: R425.1 R433.2 R441.2 U48.4(S7)
NetR443_2: R443.2 U49.1(GPI)
NetR445_2: R445.2 U52.22(B1)
NetTP23_1: TP23.1 U52.7(A6)
NetTP24_1: TP24.1 U52.17(B6)
NetTP25_1: TP25.1 U51.10(A9)
NetTP26_1: TP26.1 U51.14(B9)
NetU51_23: U51.23(~{OE}) U52.23(~{OE}) U53.4(Y)

Not connected (* = marked no-connect by the designer): U48 7(NC)*; U51 1(NC)*; U52 1(NC)*; U53 1(NC)*

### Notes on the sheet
- TMUX1308-Q1
- TPLD1201-Q1
- Not sure what will be connected to TMUX1308. Added 0 ohms dividers, PU, and PD just in case.
- (near D55) Logic circuit for PMIC WAKE 2. Diode ORed with button, and ETH INH.
  Uses LPM threshold signals from smart fuse devices, MSDI, and CAN FD Light Commander
- Logic circuit for RESET Signals. Can reset from PORz, WARMRST, or MCU
- SN74CBTLV3861-Q1
- Disconnect signals from MCU during LPM operation.
- (near R445) Disconnect signals from MCU during LPM operation.
- OE = HI not connected to MCU
  OE = LO connected to MCU
  OE needs to be HI in LPM
  PORz = HI in normal operation

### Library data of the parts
C373 = CMP-0006949-5: CAP, CERM, 4.7 uF, 10 V, +/- 10%, X5R, 0603; Manufacturer: Kemet; TaMin_C: -55°C; ESR_ohm: 6m; Polarized: N; SizeAreaWB_mm2: 4.68; Value1: 0.006 ohm; U/M: EA; Value: 4.7uF; TaMax_C: 85°C; SizeZ_mm: 1; SizeX_mm: 1.6; SizeY_mm: 0.8; SizeArea_mm2: 1.28; Cap_F: 4.7µF; IRMS_A: 7.24A; AEC Category: Q200
C374-C381 = CMP-0095668-2: Ceramic Capacitor 10nF ±10% 50V X7R 0603; Manufacturer: Murata; SizeZ_mm: 0.9mm; TempCo: 15%; AEC Grade: Grade 1; AEC Qualified: Yes
C382-C385 = CMP-0007135-2: CAP, CERM, 0.1 uF, 16 V, +/- 10%, X7R, AEC-Q200 Grade 1, 0603; Manufacturer: MuRata; TaMin_C: -55°C; Polarized: N; SizeAreaWB_mm2: 4.68; Value1: Unknown; U/M: EA; Value: 0.1uF; TaMax_C: 125°C; SizeZ_mm: 1; SizeX_mm: 1.6; SizeY_mm: 0.8; SizeArea_mm2: 1.28; AEC Qualified: Y; AEC Category: Q200
D55 = CMP-0028880-3: Diode, Schottky, 20 V, 0.5 A, AEC-Q101, SOD-523; Manufacturer: ON Semiconductor; Green_Lifecycle: Not Set; Vr_V: 20V; TJmax_C: 125°C; SizeArea_mm2: 1.53; SizeZ_mm: 0.65; Green_REACh: Incomplete; AEC Qualified: Y; AEC Category: Q101; Io_A: 500mA; Value: 20V; Vf_V: 480mV; Value1: 0.5A; SizeY_mm: 0.9; SizeX_mm: 1.7; Value2: 0.48V; SizeAreaWB_mm2: 5.13
D58 = CMP-0005797-3: Diode, Zener, 3.3 V, 500 mW, SOD-123; Manufacturer: Diodes Inc.; SizeZ_mm: 1.35; SizeX_mm: 3.85; Value1: 0.5W; RJA_CperW: 350; SizeAreaWB_mm2: 13.095; Power_W: 500mW; SizeArea_mm2: 6.545; SizeY_mm: 1.7; AEC Category: Q101
R418-R441 R443 R445 = CMP-0025697-4: RES, 0, 5%, 0.1 W, AEC-Q200 Grade 0, 0603; Manufacturer: Vishay-Dale; Power_W: 100mW; TempCo: 200 ppm/C; Value_Code: 0000; Value: 0; EIA_Code: E24; SizeX_mm: 1.6; SizeY_mm: 0.8; SizeZ_mm: 1; Value2: 0.1W; SizeArea_mm2: 1.28; CompType: Resistor; AEC Qualified: Y; VDC_V: 75V; AEC Category: Q200
R442 = CMP-0025764-4: RES, 270 k, 5%, 0.1 W, AEC-Q200 Grade 0, 0603; Manufacturer: Vishay-Dale; Power_W: 100mW; TempCo: 200 ppm/C; Value: 270k; EIA_Code: E24; SizeX_mm: 1.6; SizeY_mm: 0.8; SizeZ_mm: 1; Value2: 0.1W; SizeArea_mm2: 1.28; AEC Qualified: Y; VDC_V: 75V; AEC Category: Q200; AEC Grade: 0
R444 = CMP-0022008-4: RES, 110 k, 1%, 0.1 W, AEC-Q200 Grade 0, 0603; Manufacturer: Vishay-Dale; Power_W: 100mW; TempCo: 100 ppm/C; Value: 110k; EIA_Code: E96; SizeX_mm: 1.6; SizeY_mm: 0.8; SizeZ_mm: 1; Value2: 0.1W; SizeArea_mm2: 1.28; AEC Qualified: Y; VDC_V: 75V; AEC Category: Q200; AEC Grade: 0
TP23-TP26 = CMP-0078143-3: TEST POINT.  No entry in BOM.
U48 = CMP-0123545-1: Automotive 5V, bidirectional 8: 1, 1-channel multiplexer with injection current control & 1.8V logic 16-TSSOP -40 to...; Manufacturer: Texas Instruments; SizeZ_mm: 1.2mm; AEC Qualified: Yes; -3Db Bandwith: 500MHz; AEC Grade: Grade 1; Max Supply Voltage: 5.5V; Min Supply Voltage: 1.62V; Mux Demux Ratio: 8:1; Nominal Supply Current: 1uA; On State Resistance: 75Ω; PositionCount: 1; Standoff Height: 0.05mm; TaMax_C: +125°C; TaMin_C: -40°C; TJmax_C: +150°C
U49 U50 = CMP-0123925-1: Automotive Programmable logic device with eight general purpose inputs or outputs 10-VSSOP -40 to 125; Manufacturer: Texas Instruments; SizeZ_mm: 1.1mm; AEC Qualified: Yes; Standoff Height: 0.05mm
U51 U52 = CMP-0123129-1: Automotive 3.3-V, 1:1 (SPST), 10-channel general-purpose FET bus switch; Manufacturer: Texas Instruments; SizeZ_mm: 1.2mm; AEC Qualified: Yes; -3Db Bandwith: 200MHz; AEC Grade: Grade 3; Max Supply Voltage: 3.6V; Min Supply Voltage: 2.3V; Nominal Supply Current: 10uA; On State Resistance: 5Ω; PositionCount: 10; Standoff Height: 0.05mm; TaMax_C: +85°C; TaMin_C: -40°C
U53 = CMP-0051630-2: Single Schmitt-Trigger Inverter Gate, DBV0005A (SOT-23-5); Manufacturer: Texas Instruments; ICC @ Nom Voltage(Max)(mA): 0.01; Output Drive (IOL/IOH)(Max)(mA): 8/-8; Bits(#): 1; VCC(Min)(V): 2; Input Type: CMOS; Rating: Catalog; 3-State Output: No; tpd @ Nom Voltage(Max)(ns): 8; Schmitt Trigger: Yes; Logic: Inverting; VCC(Max)(V): 5.5; F @ Nom Voltage(Max)(Mhz): 75; Voltage(Nom)(V): 5; AEC Category: Q200; AEC Qualified: N; CompType: IC; SizeAreaWB_mm2: 14.82; SizeArea_mm2: 8.12; SizeX_mm: 2.8; SizeY_mm: 2.9; SizeZ_mm: 1.45

## Sheet TIC12400-Q1.SchDoc
size 431 x 279 mm; Date: Not shown in title block; ApprovedBy: Not shown in title block; CheckedBy: Not shown in title block; Author: Not shown in title block; CompanyName: Not shown in title block; Engineer: Not shown in title block; Organization: Not shown in title block; Address1: Not shown in title block; Address2: Not shown in title block; Address3: Not shown in title block; Address4: Not shown in title block; DocumentNumber: 1; Revision: Use project parameter SCH_Rev; SheetNumber: 27; SheetTotal: 30; PageSetup: Record=PageOptions¦CenterHorizontal=True¦CenterVertical=True¦PrintScale=1.00¦XCorrection=1.00¦YCorrection=1.00¦PrintKind=0¦BorderSize=5000000¦LeftOffset=0¦BottomOffset=0¦Orientation=2¦PaperLength=1000¦PaperWidth=1000¦Scale=100¦PaperSource=15¦PrintQuality=600¦MediaType=1¦DitherType=10¦PaperKind=Letter¦PrintScaleMode=1
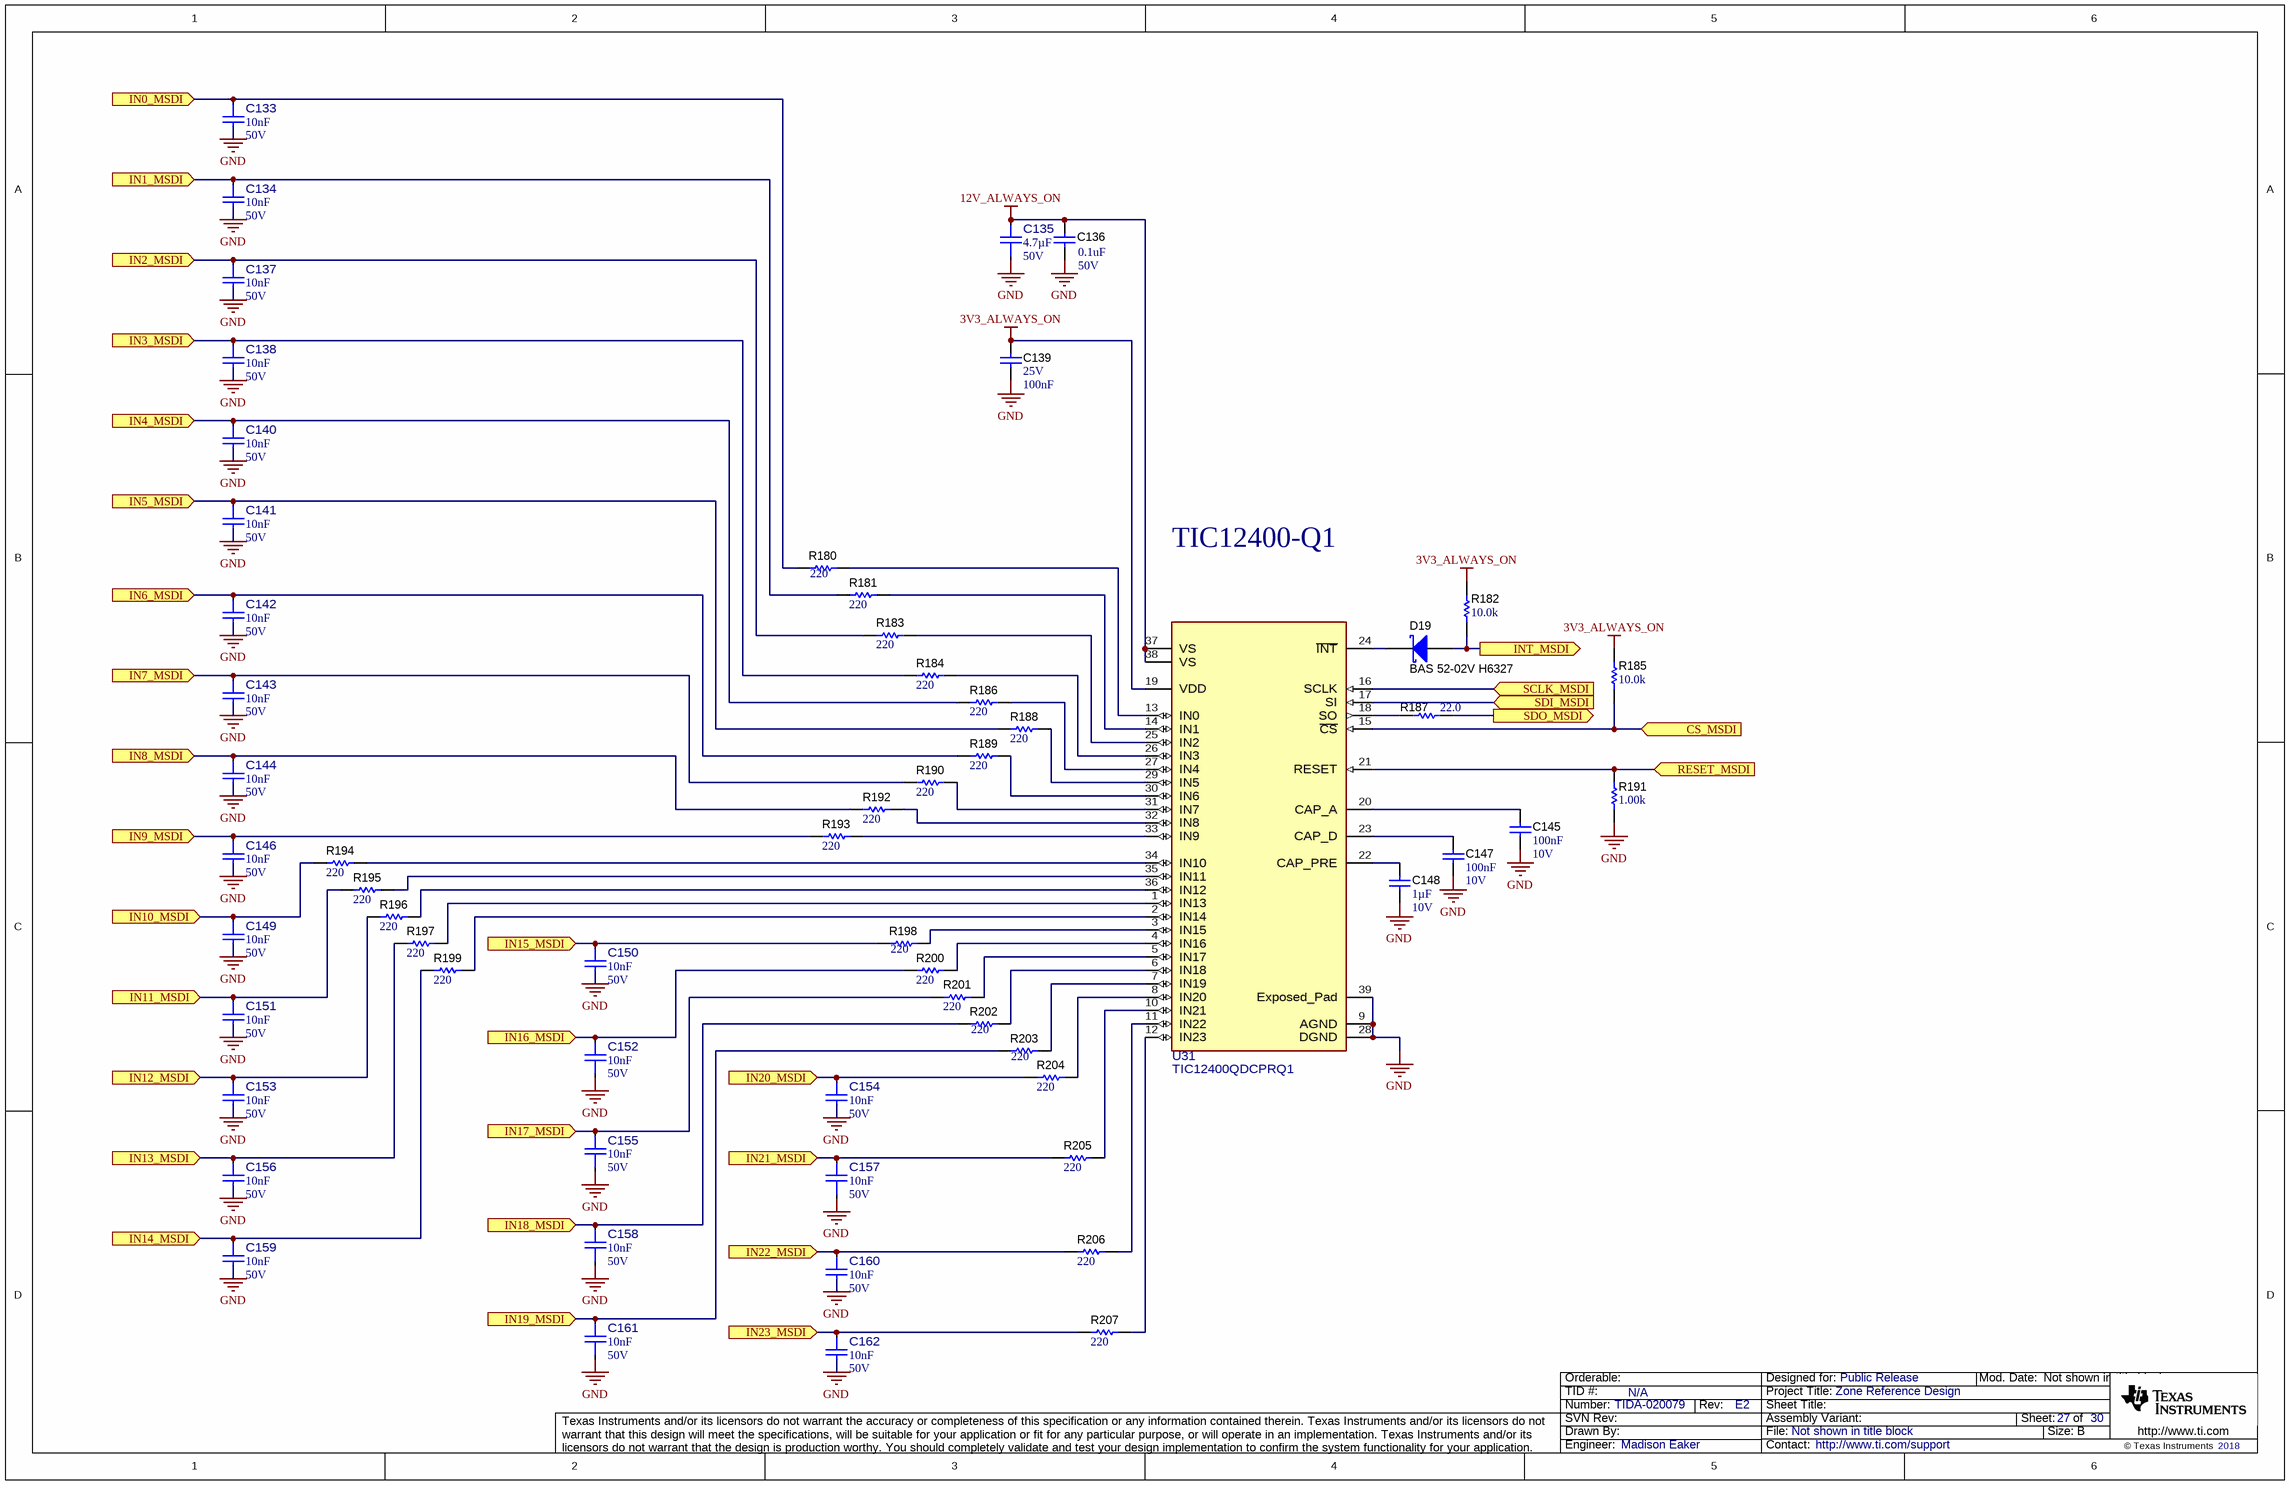
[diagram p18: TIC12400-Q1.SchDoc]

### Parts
C133  Cap_F: 10nF  VDC_V: 50V  [FP-GCE188R71H103KA01D_0603-MFG]  (hidden comment: GCE188R71H103KA01D)
C134  Cap_F: 10nF  VDC_V: 50V  [FP-GCE188R71H103KA01D_0603-MFG]  (hidden comment: GCE188R71H103KA01D)
C135  Cap_F: 4.7µF  VDC_V: 50V  [FP-CGA4J1X7R1H475K125AC_0805-MFG]  (hidden comment: CGA4J1X7R1H475K125AC)
C136  VDC_V: 50V  ValueDisplayed: 0.1uF  [0402]  (hidden comment: GCM155R71H104KE02D)
C137  Cap_F: 10nF  VDC_V: 50V  [FP-GCE188R71H103KA01D_0603-MFG]  (hidden comment: GCE188R71H103KA01D)
C138  Cap_F: 10nF  VDC_V: 50V  [FP-GCE188R71H103KA01D_0603-MFG]  (hidden comment: GCE188R71H103KA01D)
C139  VDC_V: 25V  Cap_F: 100nF  [0603]  (hidden comment: GCM188R71E104KA57D)
C140  Cap_F: 10nF  VDC_V: 50V  [FP-GCE188R71H103KA01D_0603-MFG]  (hidden comment: GCE188R71H103KA01D)
C141  Cap_F: 10nF  VDC_V: 50V  [FP-GCE188R71H103KA01D_0603-MFG]  (hidden comment: GCE188R71H103KA01D)
C142  Cap_F: 10nF  VDC_V: 50V  [FP-GCE188R71H103KA01D_0603-MFG]  (hidden comment: GCE188R71H103KA01D)
C143  Cap_F: 10nF  VDC_V: 50V  [FP-GCE188R71H103KA01D_0603-MFG]  (hidden comment: GCE188R71H103KA01D)
C144  Cap_F: 10nF  VDC_V: 50V  [FP-GCE188R71H103KA01D_0603-MFG]  (hidden comment: GCE188R71H103KA01D)
C145  Cap_F: 100nF  VDC_V: 10V  [0603]  (hidden comment: 885012206020)
C146  Cap_F: 10nF  VDC_V: 50V  [FP-GCE188R71H103KA01D_0603-MFG]  (hidden comment: GCE188R71H103KA01D)
C147  Cap_F: 100nF  VDC_V: 10V  [0603]  (hidden comment: 885012206020)
C148  Cap_F: 1µF  VDC_V: 10V  [0603]  (hidden comment: LMK107B7105KA-T)
C149  Cap_F: 10nF  VDC_V: 50V  [FP-GCE188R71H103KA01D_0603-MFG]  (hidden comment: GCE188R71H103KA01D)
C150  Cap_F: 10nF  VDC_V: 50V  [FP-GCE188R71H103KA01D_0603-MFG]  (hidden comment: GCE188R71H103KA01D)
C151  Cap_F: 10nF  VDC_V: 50V  [FP-GCE188R71H103KA01D_0603-MFG]  (hidden comment: GCE188R71H103KA01D)
C152  Cap_F: 10nF  VDC_V: 50V  [FP-GCE188R71H103KA01D_0603-MFG]  (hidden comment: GCE188R71H103KA01D)
C153  Cap_F: 10nF  VDC_V: 50V  [FP-GCE188R71H103KA01D_0603-MFG]  (hidden comment: GCE188R71H103KA01D)
C154  Cap_F: 10nF  VDC_V: 50V  [FP-GCE188R71H103KA01D_0603-MFG]  (hidden comment: GCE188R71H103KA01D)
C155  Cap_F: 10nF  VDC_V: 50V  [FP-GCE188R71H103KA01D_0603-MFG]  (hidden comment: GCE188R71H103KA01D)
C156  Cap_F: 10nF  VDC_V: 50V  [FP-GCE188R71H103KA01D_0603-MFG]  (hidden comment: GCE188R71H103KA01D)
C157  Cap_F: 10nF  VDC_V: 50V  [FP-GCE188R71H103KA01D_0603-MFG]  (hidden comment: GCE188R71H103KA01D)
C158  Cap_F: 10nF  VDC_V: 50V  [FP-GCE188R71H103KA01D_0603-MFG]  (hidden comment: GCE188R71H103KA01D)
C159  Cap_F: 10nF  VDC_V: 50V  [FP-GCE188R71H103KA01D_0603-MFG]  (hidden comment: GCE188R71H103KA01D)
C160  Cap_F: 10nF  VDC_V: 50V  [FP-GCE188R71H103KA01D_0603-MFG]  (hidden comment: GCE188R71H103KA01D)
C161  Cap_F: 10nF  VDC_V: 50V  [FP-GCE188R71H103KA01D_0603-MFG]  (hidden comment: GCE188R71H103KA01D)
C162  Cap_F: 10nF  VDC_V: 50V  [FP-GCE188R71H103KA01D_0603-MFG]  (hidden comment: GCE188R71H103KA01D)
D19  BAS 52-02V H6327  [SOD-523]
R180  ValueDisplayed: 220  [0603]  (hidden comment: MCT06030C2200FP500)
R181  ValueDisplayed: 220  [0603]  (hidden comment: MCT06030C2200FP500)
R182  ValueDisplayed: 10.0k  [0603]  (hidden comment: ERJ-3EKF1002V)
R183  ValueDisplayed: 220  [0603]  (hidden comment: MCT06030C2200FP500)
R184  ValueDisplayed: 220  [0603]  (hidden comment: MCT06030C2200FP500)
R185  ValueDisplayed: 10.0k  [0603]  (hidden comment: ERJ-3EKF1002V)
R186  ValueDisplayed: 220  [0603]  (hidden comment: MCT06030C2200FP500)
R187  ValueDisplayed: 22.0  [0201]  (hidden comment: RC0201FR-0722RL)
R188  ValueDisplayed: 220  [0603]  (hidden comment: MCT06030C2200FP500)
R189  ValueDisplayed: 220  [0603]  (hidden comment: MCT06030C2200FP500)
R190  ValueDisplayed: 220  [0603]  (hidden comment: MCT06030C2200FP500)
R191  ValueDisplayed: 1.00k  [0603]  (hidden comment: RT0603BRD071KL)
R192  ValueDisplayed: 220  [0603]  (hidden comment: MCT06030C2200FP500)
R193  ValueDisplayed: 220  [0603]  (hidden comment: MCT06030C2200FP500)
R194  ValueDisplayed: 220  [0603]  (hidden comment: MCT06030C2200FP500)
R195  ValueDisplayed: 220  [0603]  (hidden comment: MCT06030C2200FP500)
R196  ValueDisplayed: 220  [0603]  (hidden comment: MCT06030C2200FP500)
R197  ValueDisplayed: 220  [0603]  (hidden comment: MCT06030C2200FP500)
R198  ValueDisplayed: 220  [0603]  (hidden comment: MCT06030C2200FP500)
R199  ValueDisplayed: 220  [0603]  (hidden comment: MCT06030C2200FP500)
R200  ValueDisplayed: 220  [0603]  (hidden comment: MCT06030C2200FP500)
R201  ValueDisplayed: 220  [0603]  (hidden comment: MCT06030C2200FP500)
R202  ValueDisplayed: 220  [0603]  (hidden comment: MCT06030C2200FP500)
R203  ValueDisplayed: 220  [0603]  (hidden comment: MCT06030C2200FP500)
R204  ValueDisplayed: 220  [0603]  (hidden comment: MCT06030C2200FP500)
R205  ValueDisplayed: 220  [0603]  (hidden comment: MCT06030C2200FP500)
R206  ValueDisplayed: 220  [0603]  (hidden comment: MCT06030C2200FP500)
R207  ValueDisplayed: 220  [0603]  (hidden comment: MCT06030C2200FP500)
U31  TIC12400QDCPRQ1  [DCP0038A-MFG]

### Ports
CS_MSDI (in), IN0_MSDI (in), IN1_MSDI (in), IN2_MSDI (in), IN3_MSDI (in), IN4_MSDI (in), IN5_MSDI (in), IN6_MSDI (in), IN7_MSDI (in), IN8_MSDI (in), IN9_MSDI (in), IN10_MSDI (in), IN11_MSDI (in), IN12_MSDI (in), IN13_MSDI (in), IN14_MSDI (in), IN15_MSDI (in), IN16_MSDI (in), IN17_MSDI (in), IN18_MSDI (in), IN19_MSDI (in), IN20_MSDI (in), IN21_MSDI (in), IN22_MSDI (in), IN23_MSDI (in), INT_MSDI (out), RESET_MSDI (in), SCLK_MSDI (in), SDI_MSDI (in), SDO_MSDI (out)

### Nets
3V3_ALWAYS_ON: C139.2 R182.1 R185.1 U31.19(VDD)
12V_ALWAYS_ON: C135.2 C136.1 U31.37(VS) U31.38(VS)
GND: C133.1 C134.1 C135.1 C136.2 C137.1 C138.1 C139.1 C140.1 C141.1 C142.1 C143.1 C144.1 C145.1 C146.1 C147.1 C148.1 C149.1 C150.1 C151.1 C152.1 C153.1 C154.1 C155.1 C156.1 C157.1 C158.1 C159.1 C160.1 C161.1 C162.1 R191.2 U31.9(AGND) U31.28(DGND) U31.39(Exposed_Pad)
CS_IO_1_MUX: R185.2 U31.15(~{CS}) ; port CS_MSDI
IN0_MSDI: C133.2 R180.1 ; port IN0_MSDI
IN1_MSDI: C134.2 R181.1 ; port IN1_MSDI
IN2_MSDI: C137.2 R183.1 ; port IN2_MSDI
IN3_MSDI: C138.2 R184.1 ; port IN3_MSDI
IN4_MSDI: C140.2 R186.1 ; port IN4_MSDI
IN5_MSDI: C141.2 R188.1 ; port IN5_MSDI
IN6_MSDI: C142.2 R189.1 ; port IN6_MSDI
IN7_MSDI: C143.2 R190.1 ; port IN7_MSDI
IN8_MSDI: C144.2 R192.1 ; port IN8_MSDI
IN9_MSDI: C146.2 R193.1 ; port IN9_MSDI
IN10_MSDI: C149.2 R194.1 ; port IN10_MSDI
IN11_MSDI: C151.2 R195.1 ; port IN11_MSDI
IN12_MSDI: C153.2 R196.1 ; port IN12_MSDI
IN13_MSDI: C156.2 R197.1 ; port IN13_MSDI
IN14_MSDI: C159.2 R199.1 ; port IN14_MSDI
IN15_MSDI: C150.2 R198.1 ; port IN15_MSDI
IN16_MSDI: C152.2 R200.1 ; port IN16_MSDI
IN17_MSDI: C155.2 R201.1 ; port IN17_MSDI
IN18_MSDI: C158.2 R202.1 ; port IN18_MSDI
IN19_MSDI: C161.2 R203.1 ; port IN19_MSDI
IN20_MSDI: C154.2 R204.1 ; port IN20_MSDI
IN21_MSDI: C157.2 R205.1 ; port IN21_MSDI
IN22_MSDI: C160.2 R206.1 ; port IN22_MSDI
IN23_MSDI: C162.2 R207.1 ; port IN23_MSDI
INT_MSDI: D19.2(A) R182.2 ; port INT_MSDI
RESET_MSDI: R191.1 U31.21(RESET) ; port RESET_MSDI
SCLK_IO: U31.16(SCLK) ; port SCLK_MSDI
SDI_IO: U31.17(SI) ; port SDI_MSDI
SDO_IO: R187.2 ; port SDO_MSDI
NetC145_2: C145.2 U31.20(CAP_A)
NetC147_2: C147.2 U31.23(CAP_D)
NetC148_2: C148.2 U31.22(CAP_PRE)
NetD19_1: D19.1(K) U31.24(~{INT})
NetR180_2: R180.2 U31.13(IN0)
NetR181_2: R181.2 U31.14(IN1)
NetR183_2: R183.2 U31.25(IN2)
NetR184_2: R184.2 U31.26(IN3)
NetR186_2: R186.2 U31.27(IN4)
NetR187_1: R187.1 U31.18(SO)
NetR188_2: R188.2 U31.29(IN5)
NetR189_2: R189.2 U31.30(IN6)
NetR190_2: R190.2 U31.31(IN7)
NetR192_2: R192.2 U31.32(IN8)
NetR193_2: R193.2 U31.33(IN9)
NetR194_2: R194.2 U31.34(IN10)
NetR195_2: R195.2 U31.35(IN11)
NetR196_2: R196.2 U31.36(IN12)
NetR197_2: R197.2 U31.1(IN13)
NetR198_2: R198.2 U31.3(IN15)
NetR199_2: R199.2 U31.2(IN14)
NetR200_2: R200.2 U31.4(IN16)
NetR201_2: R201.2 U31.5(IN17)
NetR202_2: R202.2 U31.6(IN18)
NetR203_2: R203.2 U31.7(IN19)
NetR204_2: R204.2 U31.8(IN20)
NetR205_2: R205.2 U31.10(IN21)
NetR206_2: R206.2 U31.11(IN22)
NetR207_2: R207.2 U31.12(IN23)

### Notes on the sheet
- TIC12400-Q1

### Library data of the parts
C133 C134 C137 C138 C140-C144 C146 C149-C162 = CMP-0095668-2: as C374 on sheet MUXes and TPLD
C135 = CMP-0090082-1: Cap Ceramic 4.7uF 50V X7R 10% Pad SMD 0805 +125°C Automotive T/R; Manufacturer: TDK Corporation; SizeZ_mm: 1.45mm; Tolerance_%: 0.1%; AEC Qualified: Yes; TempCo: 15%; AEC Grade: Grade 1; Value: 4.7µF
C136 = CMP-0006356-2: CAP, CERM, 0.1 uF, 50 V, +/- 10%, X7R, AEC-Q200 Grade 1, 0402; Manufacturer: MuRata; TaMin_C: -55°C; Polarized: N; SizeAreaWB_mm2: 3; Value1: Unknown; U/M: EA; Value: 0.1uF; TaMax_C: 125°C; SizeZ_mm: 0.6; SizeX_mm: 1; SizeY_mm: 0.5; AEC Qualified: Y; Cap_F: 100nF; AEC Category: Q200
C139 = CMP-0084679-1: CAP, CERM, 0.1 µF, 25 V,+/- 10%, X7R, AEC-Q200 Grade 1, 0603; Manufacturer: MuRata; TaMin_C: -55°C; SizeY_mm: 0.8; Polarized: N; SizeArea_mm2: 1.28; SizeZ_mm: 1; SizeX_mm: 1.6; AEC Qualified: Y; AEC Category: Q200; Value: 0.1uF; ValueDisplayed: 0.1µF; TaMax_C: 125°C; U/M: EA; SizeAreaWB_mm2: 4.68
C145 C147 = CMP-0064931-4: CAP, CERM, 0.1 uF, 10 V,+/- 10%, X7R, 0603; Manufacturer: Wurth Elektronik; TaMin_C: -55°C; Polarized: N; SizeAreaWB_mm2: 4.68; Value1: Unknown; U/M: EA; Value: 0.1uF; TaMax_C: 125°C; SizeZ_mm: 1; SizeX_mm: 1.6; SizeY_mm: 0.8; SizeArea_mm2: 1.28; AEC Category: Q200
C148 = CMP-0080632-1: CAP, CERM, 1 µF, 10 V,+/- 10%, X7R, 0603; Manufacturer: Taiyo Yuden; SizeAreaWB_mm2: 4.68; SizeArea_mm2: 1.28; AEC Qualified: N; AEC Category: Q200; Value: 1uF; TaMax_C: 125°C; SizeZ_mm: 1; Green_REACh: Incomplete; TaMin_C: -55°C; SizeY_mm: 0.8; Green_Lifecycle: Active; U/M: EA; SizeX_mm: 1.6
D19 = CMP-0028606-3: Diode, Schottky, 45 V, 0.75 A, SOD-523; Manufacturer: Infineon Technologies; Value: 45V; Value1: 0.75A; AEC Category: Q101; Vf_V: 600mV; SizeZ_mm: 0.65; Green_Lifecycle: Not Set; SizeAreaWB_mm2: 5.13; SizeY_mm: 0.9; TJmax_C: 150°C; Value2: 0.6V; Green_REACh: Incomplete; Io_A: 750mA; SizeArea_mm2: 1.53; SizeX_mm: 1.7
R180 R181 R183 R184 R186 R188-R190 R192-R207 = CMP-0022733-1: RES, 220, 1%, 0.125 W, 0603; Manufacturer: Vishay/Beyschlag; Power_W: 125mW; TempCo: 50 ppm/C; Value_Code: 220R; U/M: EA; Value: 220; SizeX_mm: 1.6; SizeY_mm: 0.8; SizeZ_mm: 1; Value2: 0.125W; SizeArea_mm2: 1.28; AEC Qualified: N; VDC_V: 75V; AEC Category: Q200
R182 R185 = CMP-0022684-2: RES, 10.0 k, 1%, 0.1 W, 0603; Manufacturer: Panasonic; Power_W: 100mW; TempCo: 100 ppm/C; Value_Code: 10k0; U/M: EA; Value: 10.0k; EIA_Code: E96; Res_ohm: 10k; SizeX_mm: 1.6; SizeY_mm: 0.8; SizeZ_mm: 1; Value2: 0.1W; SizeArea_mm2: 1.28; VDC_V: 75V; AEC Category: Q200
R187 = CMP-0027500-1: RES, 22.0, 1%, 0.05 W, 0201; Manufacturer: Yageo America; Power_W: 50mW; TempCo: 200 ppm/C; Value_Code: 22R0; U/M: EA; Value: 22.0; Res_ohm: 22; SizeX_mm: 0.6; SizeY_mm: 0.3; SizeZ_mm: 0.26; Value2: 0.05W; SizeArea_mm2: 0.18; AEC Qualified: N; VDC_V: 25V; AEC Category: Q200
R191 = CMP-0023919-1: RES, 1.00 k, 0.1%, 0.1 W, 0603; Manufacturer: Yageo America; Power_W: 100mW; TempCo: 25 ppm/C; Value_Code: 1k00; U/M: EA; Value: 1.00k; EIA_Code: E192; Res_ohm: 1k; SizeX_mm: 1.6; SizeY_mm: 0.8; SizeZ_mm: 1; Value2: 0.1W; SizeArea_mm2: 1.28; VDC_V: 75V; AEC Category: Q200
U31 = CMP-0088400-1: Automotive, Switch Monitoring Interface 38-HTSSOP; Manufacturer: Texas Instruments; Standoff Height: 0.05mm; Max Supply Voltage: 35V; SizeZ_mm: 1.2mm; Interface: SPI; Min Supply Voltage: 4.5V; AEC Qualified: Yes; TJmax_C: +150°C; AEC Grade: Grade 1; TaMin_C: -40°C; TaMax_C: +125°C

## Sheet IO Expanders.SchDoc
size 431 x 279 mm; Date: Not shown in title block; ApprovedBy: Not shown in title block; CheckedBy: Not shown in title block; Author: Not shown in title block; CompanyName: Not shown in title block; Engineer: Not shown in title block; Organization: Not shown in title block; Address1: Not shown in title block; Address2: Not shown in title block; Address3: Not shown in title block; Address4: Not shown in title block; DocumentNumber: 1; Revision: Use project parameter SCH_Rev; SheetNumber: 29; SheetTotal: 30; PageSetup: Record=PageOptions¦CenterHorizontal=True¦CenterVertical=True¦PrintScale=1.00¦XCorrection=1.00¦YCorrection=1.00¦PrintKind=0¦BorderSize=5000000¦LeftOffset=0¦BottomOffset=0¦Orientation=2¦PaperLength=1000¦PaperWidth=1000¦Scale=100¦PaperSource=15¦PrintQuality=600¦MediaType=1¦DitherType=10¦PaperKind=Letter¦PrintScaleMode=1
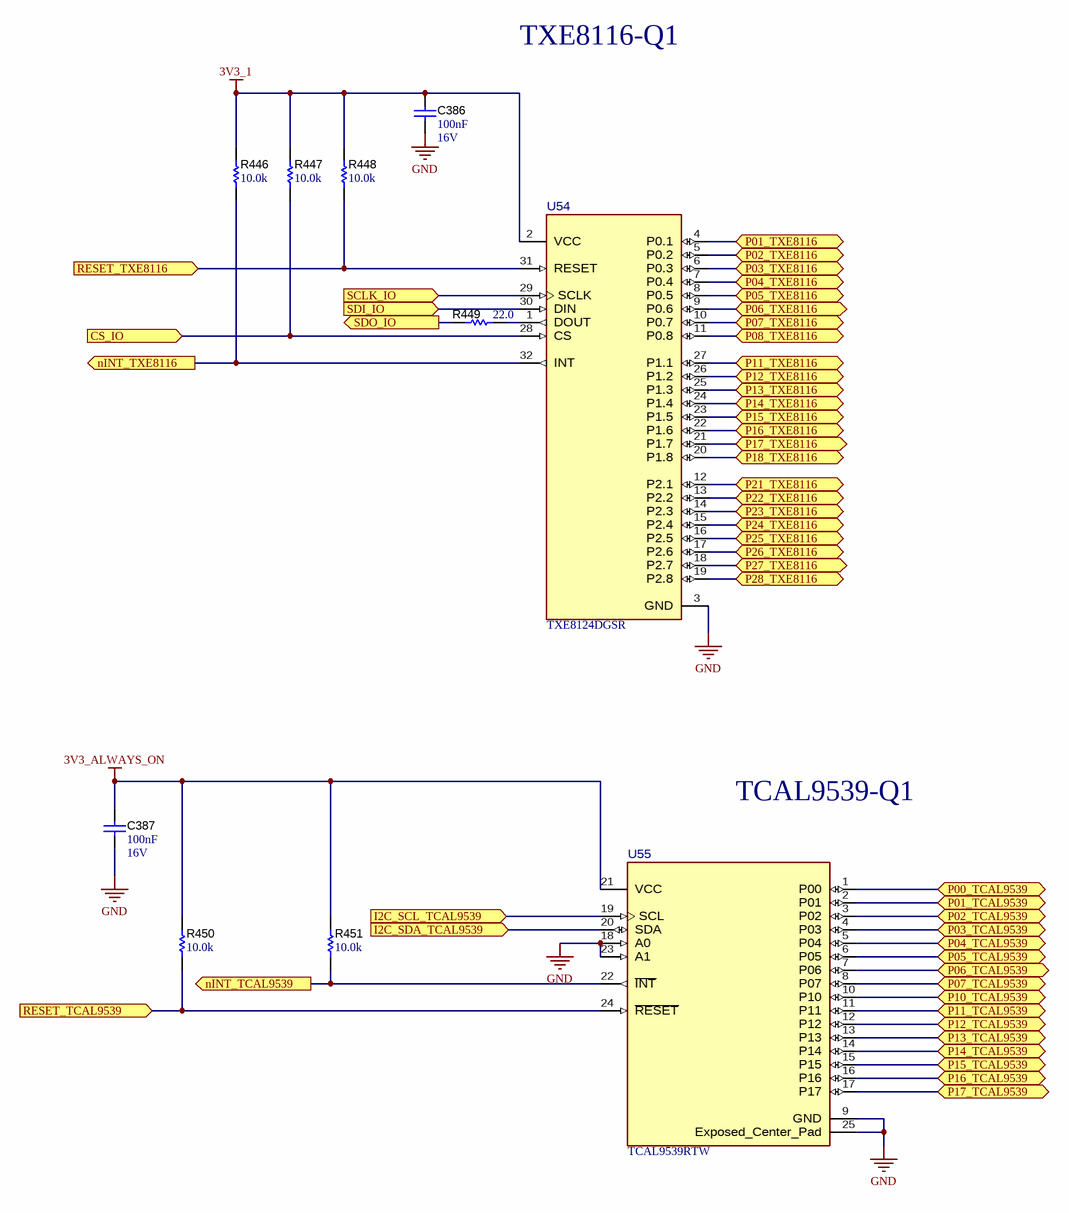
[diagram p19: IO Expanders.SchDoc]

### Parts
C386  Cap_F: 100nF  VDC_V: 16V  [0603]  (hidden comment: GCM188R71C104KA37J)
C387  Cap_F: 100nF  VDC_V: 16V  [0603]  (hidden comment: GCM188R71C104KA37J)
R446  ValueDisplayed: 10.0k  [0603]  (hidden comment: ERJ-3EKF1002V)
R447  ValueDisplayed: 10.0k  [0603]  (hidden comment: ERJ-3EKF1002V)
R448  ValueDisplayed: 10.0k  [0603]  (hidden comment: ERJ-3EKF1002V)
R449  ValueDisplayed: 22.0  [0201]  (hidden comment: RC0201FR-0722RL)
R450  ValueDisplayed: 10.0k  [0603]  (hidden comment: ERJ-3EKF1002V)
R451  ValueDisplayed: 10.0k  [0603]  (hidden comment: ERJ-3EKF1002V)
U54  TXE8124DGSR  [DGS0032A-MFG]
U55  TCAL9539RTW  [RTW0024B-MFG]

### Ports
CS_IO (in), I2C_SCL_TCAL9539 (in), I2C_SDA_TCAL9539 (in), nINT_TCAL9539 (out), nINT_TXE8116 (out), P00_TCAL9539 (bidir), P01_TCAL9539 (bidir), P01_TXE8116 (bidir), P02_TCAL9539 (bidir), P02_TXE8116 (bidir), P03_TCAL9539 (bidir), P03_TXE8116 (bidir), P04_TCAL9539 (bidir), P04_TXE8116 (bidir), P05_TCAL9539 (bidir), P05_TXE8116 (bidir), P06_TCAL9539 (bidir), P06_TXE8116 (bidir), P07_TCAL9539 (bidir), P07_TXE8116 (bidir), P08_TXE8116 (bidir), P10_TCAL9539 (bidir), P11_TCAL9539 (bidir), P11_TXE8116 (bidir), P12_TCAL9539 (bidir), P12_TXE8116 (bidir), P13_TCAL9539 (bidir), P13_TXE8116 (bidir), P14_TCAL9539 (bidir), P14_TXE8116 (bidir), P15_TCAL9539 (bidir), P15_TXE8116 (bidir), P16_TCAL9539 (bidir), P16_TXE8116 (bidir), P17_TCAL9539 (bidir), P17_TXE8116 (bidir), P18_TXE8116 (bidir), P21_TXE8116 (bidir), P22_TXE8116 (bidir), P23_TXE8116 (bidir), P24_TXE8116 (bidir), P25_TXE8116 (bidir), P26_TXE8116 (bidir), P27_TXE8116 (bidir), P28_TXE8116 (bidir), RESET_TCAL9539 (in), RESET_TXE8116 (in), SCLK_IO (in), SDI_IO (in), SDO_IO (out)

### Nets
3V3_1: C386.1 R446.1 R447.1 R448.1 U54.2(VCC)
3V3_ALWAYS_ON: C387.1 R450.1 R451.1 U55.21(VCC)
GND: C386.2 C387.2 U54.3(GND) U55.9(GND) U55.18(A0) U55.23(A1) U55.25(Exposed_Center_Pad)
BRAKE_DRV8714: U54.10(P0.7) ; port P07_TXE8116
ClassD_AMP_FAULT: U54.5(P0.2) ; port P02_TXE8116
ClassD_AMP_SHTDN: U54.6(P0.3) ; port P03_TXE8116
ClassD_AMP_STBY: U54.4(P0.1) ; port P01_TXE8116
CS_IO: R447.2 U54.28(CS) ; port CS_IO
DIAGEN_TPS1HC04: U54.18(P2.7) ; port P27_TXE8116
DIAGEN_TPS1HC30: U54.27(P1.1) ; port P11_TXE8116
DIAGEN_TPS2HC08: U54.15(P2.4) ; port P24_TXE8116
DIAGEN_TPS4HC120: U55.14(P14) ; port P14_TCAL9539
DRVOFF_DRV8145: U54.8(P0.5) ; port P05_TXE8116
EN1_TPS2HC08: U54.12(P2.1) ; port P21_TXE8116
EN1_TPS4HC120: U55.10(P10) ; port P10_TCAL9539
EN2_TPS2HC08: U54.13(P2.2) ; port P22_TXE8116
EN2_TPS4HC120: U55.11(P11) ; port P11_TCAL9539
EN3_TPS4HC120: U55.12(P12) ; port P12_TCAL9539
EN4_TPS4HC120: U55.13(P13) ; port P13_TCAL9539
EN_ETH: U55.2(P01) ; port P01_TCAL9539
EN_TPS1HC04: U54.17(P2.6) ; port P26_TXE8116
EN_TPS1HC30: U54.21(P1.7) ; port P17_TXE8116
EN_TPS1214: U55.7(P06) ; port P06_TCAL9539
FLT/: U55.8(P07) ; port P07_TCAL9539
FLT_I_TPS1211: U54.22(P1.6) ; port P16_TXE8116
FLT_T_TPS1211: U54.23(P1.5) ; port P15_TXE8116
FLT_TPS2HCS05: U55.5(P04) ; port P04_TCAL9539
FLT_TPS2HCS10/08: U55.6(P05) ; port P05_TCAL9539
GPIO81: R446.2 U54.32(INT) ; port nINT_TXE8116
I2C0_SCL: U55.19(SCL) ; port I2C_SCL_TCAL9539
I2C0_SDA: U55.20(SDA) ; port I2C_SDA_TCAL9539
INP_G_TPS1211: U54.24(P1.4) ; port P14_TXE8116
INP_TPS1211: U54.25(P1.3) ; port P13_TXE8116
LATCH_TPS1HC30: U54.11(P0.8) ; port P08_TXE8116
LPM_TPS4HC120: U55.4(P03) ; port P03_TCAL9539
nFAULT_DRV8145: U54.9(P0.6) ; port P06_TXE8116
nFAULT_TPS1HC04: U54.19(P2.8) ; port P28_TXE8116
nFAULT_TPS1HC30: U54.20(P1.8) ; port P18_TXE8116
nFAULT_TPS2HC08: U54.16(P2.5) ; port P25_TXE8116
nFAULT_TPS4HC120: U55.17(P17) ; port P17_TCAL9539
nFLT_DRV8714: U54.26(P1.2) ; port P12_TXE8116
nINT_TCAL9539: R451.2 U55.22(~{INT}) ; port nINT_TCAL9539
nSLEEP_DRV81242: U54.7(P0.4) ; port P04_TXE8116
P15_TCAL9539: U55.15(P15) ; port P15_TCAL9539
P16_TCAL9539: U55.16(P16) ; port P16_TCAL9539
P23_TXE8116: U54.14(P2.3) ; port P23_TXE8116
RESET_ETH: U55.1(P00) ; port P00_TCAL9539
RESET_TCAL: R450.2 U55.24(~{RESET}) ; port RESET_TCAL9539
RESET_TXE: R448.2 U54.31(RESET) ; port RESET_TXE8116
SCLK_IO: U54.29(SCLK) ; port SCLK_IO
SDI_IO: U54.30(DIN) ; port SDI_IO
SDO_IO: R449.1 ; port SDO_IO
WAKE: U55.3(P02) ; port P02_TCAL9539
NetR449_2: R449.2 U54.1(DOUT)

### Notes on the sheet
- TXE8116-Q1
- TCAL9539-Q1

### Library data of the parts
C386 C387 = CMP-0007135-2: as C382 on sheet MUXes and TPLD
R446-R448 R450 R451 = CMP-0022684-2: as R182 on sheet TIC12400-Q1
R449 = CMP-0027500-1: as R187 on sheet TIC12400-Q1
U54 = CMP-0122824-1: Manufacturer: Texas Instruments; SizeZ_mm: 1.1mm; Standoff Height: 0.05mm
U55 = CMP-0094311-1: Low-Voltage Translating, 16-Bit I2C-Bus, SMBus I/O Expander with Interrupt Output, Reset, and Agile I/O Configuration Registers; Manufacturer: Texas Instruments; TaMax_C: +125°C; AEC Qualified: No; Max Supply Voltage: 3.6V; Min Supply Voltage: 1.08V; SizeZ_mm: 0.8mm; Interface: I2C,SMBus; Nominal Supply Current: 2-11uA; Frequency_Fixed: 1MHz; Standoff Height: 0mm; Number Of I/Os: 16; TaMin_C: -40°C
